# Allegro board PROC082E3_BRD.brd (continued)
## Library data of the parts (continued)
L1-L18 L20 L23 L25 L28-L30 = INDUCTOR
L19 L21 L22 L24 = INDUCTOR_DLW31S
R1-R52 R57 R61-R73 R78 R81-R99 R102 R106 R108-R119 R121-R123 R125 R128-R132 R135-R141 R144-R158 R160-R164 R166-R214 R222 R223 R228 R230 R232-R234 R236 R239 R241 R243-R245 R253-R259 = RESISTOR
R159 R165 = RESISTOR: signal model: RESISTOR_RES0402_22E_22E
TP1-TP45 TP50-TP53 TP55 TP56 = TESTPOINT
U1 U5 U10 U14 = TPD2E001DRLR_SOT-5
U3 U4 U7 U8 U12 U13 U16-U18 U23 U26 U27 = TPS25940_WQFN20_TI
U9 U24 U25 = DS90UB9702-Q1_VQFNP88
U19 = TPS62827DMQR_VSONHR6
U20 = CAT24C256WI-GT3_SOIC8
U21 = OSC4_ASDMB
U22 = LMK00105SQ_WQFN24
U28 = TPS54620_QFN14
U29-U31 = TPS74801DRCR_SON10
U32 = DS90UB971-Q1_VQFN32
U33 = TPS54318RTE_QFN16
U35 = LM25085A_WSON8
U36 = MOSFET_SI7123DN

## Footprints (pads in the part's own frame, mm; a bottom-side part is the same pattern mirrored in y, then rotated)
CAP0201_0-5
  rect 0.559x0.508 smd: 1(-0.38,0) 2(0.38,0)
CAP0402_0-75
  rect 0.559x0.635 smd: 1(-0.49,0) 2(0.49,0)
CAP0603_1
  rect 0.94x1.016 smd: 1(-0.8,0) 2(0.8,0)
CAP0805_1-5
  rect 1.143x1.448 smd: 1(-0.9,0) 2(0.9,0)
CAP1206_1
  rect 1.143x1.803 smd: 1(-1.5,0) 2(1.5,0)
CAP1206_2
  rect 1.143x1.803 smd: 1(-1.5,0) 2(1.5,0)
CAP1210_2-75
  rect 0.965x2.718 smd: 1(-1.65,0) 2(1.65,0)
CAP2220_5-5
  rect 0.813x5.41 smd: 1(-2.95,0) 2(2.95,0)
CAPAE_D8CASE_8
  rect 3.15x1.6 smd: 1(-2.9,0) 2(2.9,0)
CAPAE_E12CASE_12
  rect 3.759x2.159 smd: 1(-3.45,0) 2(3.45,0)
CAPT6032C_3
  rect 2.362x2.261 smd: 1(-2.45,0) 2(2.45,0)
CON_JACK4_D4S10A-400L5-Z_P_S_T_15-4
  rect 1.295x1.295 hole 0.813: 1(0,0)
  round 1.295 hole 0.813: 2(0,-2) 3(2,-2) 4(2,0)
  round 2.007 hole 1.575: SH1(-2,2) SH4(4,2)
  round 2.007 hole 1.219: SH2(-2,-4) SH3(4,-4)
CON_JACK5_59S10H-400T5-Z_P_S_T_12-5
  rect 1.702x1.702 hole 1.016: 1(0,0)
  round 2.108 hole 1.422: 2(-2.54,-2.54) 3(-2.54,2.54) 4(2.54,2.54) 5(2.54,-2.54)
CON_JACK5_59S20X-400T5-Z_P_R_T_10-1
  rect 2.21x2.21 hole 1.524: 1(0,0)
  round 2.565 hole 1.88: 2(-2.54,-2.54) 3(-2.54,2.54) 4(2.54,2.54) 5(2.54,-2.54)
CON_PMC2X20_QTH-020-01-D-DP-A_P_S_S_4-4
  round 0.889 hole 1.016 unplated: (-9.24,2.03) (9.24,2.03)
  rect 0.305x1.448 smd: 1(-7.25,3.08) 2(-7.25,-3.09) 3(-6.75,3.08) 4(-6.75,-3.09) 5(-5.75,3.08) 6(-5.75,-3.09) 7(-5.25,3.08) 8(-5.25,-3.09) 9(-4.25,3.08) 10(-4.25,-3.09) 11(-3.75,3.08) 12(-3.75,-3.09) 13(-2.75,3.08) 14(-2.75,-3.09) 15(-2.25,3.08) 16(-2.25,-3.09) 17(-1.25,3.08) 18(-1.25,-3.09) 19(-0.75,3.08) 20(-0.75,-3.09) 21(0.25,3.08) 22(0.25,-3.09) 23(0.75,3.08) 24(0.75,-3.09) 25(1.75,3.08) 26(1.75,-3.09) 27(2.25,3.08) 28(2.25,-3.09) 29(3.25,3.08) 30(3.25,-3.09) 31(3.75,3.08) 32(3.75,-3.09) 33(4.75,3.08) 34(4.75,-3.09) 35(5.25,3.08) 36(5.25,-3.09) 37(6.25,3.08) 38(6.25,-3.09) 39(6.75,3.08) 40(6.75,-3.09)
  rect 2.54x0.635 smd: SH1(-8.445,0) SH4(8.445,0)
  rect 4.699x0.635 smd: SH2(-3.175,0) SH3(3.175,0)
CON_TB1X2_1757242_P_R_T_8-6
  rect 2.108x2.108 hole 1.422: 1(0,0)
  round 2.108 hole 1.422: 2(-5.08,0)
DFN8_19-68_120X120_0-8_EP1-7X2-1
  rect 0.787x0.305 smd: 1(-1.5,0.75) 2(-1.5,0.25) 3(-1.5,-0.25) 4(-1.5,-0.75) 5(1.5,-0.75) 6(1.5,-0.25) 7(1.5,0.25) 8(1.5,0.75)
  rect 1.702x2.108 smd: 9(0,0)
DIO_SMC_2-7
  rect 2.21x3.099 smd: 1(-3.5,0) 2(3.5,0)
EMIFIL_BLM15A_0402_0-6
  rect 0.61x0.61 smd: 1(-0.46,0) 2(0.46,0)
EMIFIL_BLM18A_0603_1
  rect 0.991x0.991 smd: 1(-0.75,0) 2(0.75,0)
EMIFIL_BLM18R_0603
  rect 0.94x1.194 smd: 1(-0.825,0) 2(0.825,0)
FUSEH_154004_380X200_SMD_3-9
  rect 4.242x3.81 smd: 1(-3.19,0) 2(3.19,0)
IND4_DLW21H_90X60_SMD_1-4
  rect 0.889x0.356 smd: 1(-0.85,-0.425) 2(0.85,-0.425) 3(0.85,0.425) 4(-0.85,0.425)
IND_74437368022_410X410_SMD_4
  rect 4.089x3.505 smd: 1(-4.75,0) 2(4.75,0)
IND_74438357010_170X170_SMD_3-1
  rect 0.991x3.708 smd: 1(-1.185,0) 2(1.185,0)
IND_744040640047_250X250_SMD_4-5
  rect 1.803x5.69 smd: 1(-2.3,0) 2(2.3,0)
IND_MLZ2012N_90X60_SMD
  rect 0.813x1.219 smd: 1(-0.9,0) 2(0.9,0)
IND_XAL1010_460X410_SMD
  rect 2.388x8.992 smd: 1(-3.325,0) 2(3.325,0)
OSC4_ASDMB_100X85_SMD
  rect 0.66x0.864 smd: 1(-0.825,-0.775) 2(0.825,-0.775) 3(0.825,0.775) 4(-0.825,0.775)
POWERPAKSO8_SI7848BDP_240X200_1-2
  rect 1.27x0.61 smd: 1(-2.67,1.905) 2(-2.67,0.635) 3(-2.67,-0.635) 4(-2.67,-1.905)
  custom 1.105x1.105 smd: 5(1.045,0)
QFN14_19-68_145X145
  rect 0.838x0.279 smd: 1(-1.725,-0.75) 7(1.725,-0.75) 8(1.725,0.75) 14(-1.725,0.75)
  rect 0.279x0.838 smd: 2(-1,-1.725) 3(-0.5,-1.725) 4(0,-1.725) 5(0.5,-1.725) 6(1,-1.725) 9(1,1.725) 10(0.5,1.725) 11(0,1.725) 12(-0.5,1.725) 13(-1,1.725)
  custom 0.512x0.512 smd: 15(0,0)
QFN16_19-68_120X120_0-8_EP1-8
  rect 0.762x0.305 smd: 1(-1.5,0.75) 2(-1.5,0.25) 3(-1.5,-0.25) 4(-1.5,-0.75) 9(1.5,-0.75) 10(1.5,-0.25) 11(1.5,0.25) 12(1.5,0.75)
  rect 0.305x0.762 smd: 5(-0.75,-1.5) 6(-0.25,-1.5) 7(0.25,-1.5) 8(0.75,-1.5) 13(0.75,1.5) 14(0.25,1.5) 15(-0.25,1.5) 16(-0.75,1.5)
  rect 1.803x1.803 smd: 17(0,0)
QFN20_19-68_120X160_0-8
  rect 0.787x0.305 smd: 1(-1.5,1.25) 2(-1.5,0.75) 3(-1.5,0.25) 4(-1.5,-0.25) 5(-1.5,-0.75) 6(-1.5,-1.25) 11(1.5,-1.25) 12(1.5,-0.75) 13(1.5,-0.25) 14(1.5,0.25) 15(1.5,0.75) 16(1.5,1.25)
  rect 0.305x0.787 smd: 7(-0.75,-2) 8(-0.25,-2) 9(0.25,-2) 10(0.75,-2) 17(0.75,2) 18(0.25,2) 19(-0.25,2) 20(-0.75,2)
  rect 1.727x2.743 smd: 21(0,0)
QFN32_19-68_200X200_1_EP3-8
  rect 0.787x0.305 smd: 1(-2.5,1.75) 2(-2.5,1.25) 3(-2.5,0.75) 4(-2.5,0.25) 5(-2.5,-0.25) 6(-2.5,-0.75) 7(-2.5,-1.25) 8(-2.5,-1.75) 17(2.5,-1.75) 18(2.5,-1.25) 19(2.5,-0.75) 20(2.5,-0.25) 21(2.5,0.25) 22(2.5,0.75) 23(2.5,1.25) 24(2.5,1.75)
  rect 0.305x0.787 smd: 9(-1.75,-2.5) 10(-1.25,-2.5) 11(-0.75,-2.5) 12(-0.25,-2.5) 13(0.25,-2.5) 14(0.75,-2.5) 15(1.25,-2.5) 16(1.75,-2.5) 25(1.75,2.5) 26(1.25,2.5) 27(0.75,2.5) 28(0.25,2.5) 29(-0.25,2.5) 30(-0.75,2.5) 31(-1.25,2.5) 32(-1.75,2.5)
  rect 3.81x3.81 smd: 33(0,0)
QFN88_19-68_480X480_0-9_EP6-8
  rect 0.787x0.305 smd: 1(-6,5.25) 2(-6,4.75) 3(-6,4.25) 4(-6,3.75) 5(-6,3.25) 6(-6,2.75) 7(-6,2.25) 8(-6,1.75) 9(-6,1.25) 10(-6,0.75) 11(-6,0.25) 12(-6,-0.25) 13(-6,-0.75) 14(-6,-1.25) 15(-6,-1.75) 16(-6,-2.25) 17(-6,-2.75) 18(-6,-3.25) 19(-6,-3.75) 20(-6,-4.25) 21(-6,-4.75) 22(-6,-5.25) 45(6,-5.25) 46(6,-4.75) 47(6,-4.25) 48(6,-3.75) 49(6,-3.25) 50(6,-2.75) 51(6,-2.25) 52(6,-1.75) 53(6,-1.25) 54(6,-0.75) 55(6,-0.25) 56(6,0.25) 57(6,0.75) 58(6,1.25) 59(6,1.75) 60(6,2.25) 61(6,2.75) 62(6,3.25) 63(6,3.75) 64(6,4.25) 65(6,4.75) 66(6,5.25)
  rect 0.305x0.787 smd: 23(-5.25,-6) 24(-4.75,-6) 25(-4.25,-6) 26(-3.75,-6) 27(-3.25,-6) 28(-2.75,-6) 29(-2.25,-6) 30(-1.75,-6) 31(-1.25,-6) 32(-0.75,-6) 33(-0.25,-6) 34(0.25,-6) 35(0.75,-6) 36(1.25,-6) 37(1.75,-6) 38(2.25,-6) 39(2.75,-6) 40(3.25,-6) 41(3.75,-6) 42(4.25,-6) 43(4.75,-6) 44(5.25,-6) 67(5.25,6) 68(4.75,6) 69(4.25,6) 70(3.75,6) 71(3.25,6) 72(2.75,6) 73(2.25,6) 74(1.75,6) 75(1.25,6) 76(0.75,6) 77(0.25,6) 78(-0.25,6) 79(-0.75,6) 80(-1.25,6) 81(-1.75,6) 82(-2.25,6) 83(-2.75,6) 84(-3.25,6) 85(-3.75,6) 86(-4.25,6) 87(-4.75,6) 88(-5.25,6)
  rect 6.807x6.807 smd: 89(0,0)
RES0201_0-5
  rect 0.457x0.432 smd: 1(-0.33,0) 2(0.33,0)
RES0402_0-5
  rect 0.559x0.635 smd: 1(-0.49,0) 2(0.49,0)
RES0603_0-5
  rect 0.635x0.991 smd: 1(-0.74,0) 2(0.74,0)
RES1206_0-75
  rect 1.067x1.753 smd: 1(-1.45,0) 2(1.45,0)
SOIC8_1-8
  rect 2.007x0.61 smd: 1(-2.4,1.905) 2(-2.4,0.635) 3(-2.4,-0.635) 4(-2.4,-1.905) 5(2.4,-1.905) 6(2.4,-0.635) 7(2.4,0.635) 8(2.4,1.905)
SOT553-5_0-6
  rect 0.66x0.254 smd: 1(-0.74,0.5) 2(-0.74,0) 3(-0.74,-0.5) 4(0.74,-0.5) 5(0.74,0.5)
TO277-3_FSV10150V_1-2
  rect 1.143x1.448 smd: 1(-2.75,-0.985) 2(-2.75,0.985)
  rect 4.648x4.14 smd: 3(1,0)
TO-252AE-3_V20PW45C_1-6
  rect 1.397x1.905 smd: 1(2.29,-3.95) 2(-2.29,-3.95)
  rect 6.096x5.969 smd: 3(0,1.915)
TP30_SMD
  round 0.762 smd: 1(0,0)
TP40_SMD
  round 1.016 smd: 1(0,0)
TP_40X65
  round 1.651 hole 1.016: 1(0,0)
TP_CIR67D40_TH_4-6
  round 1.702 hole 1.016: 1(0,0)
unnamed#2
  round 3.073 hole 3.2 unplated: (0,0)
VSON10_TPS74801-Q1_120X120_1
  rect 0.61x0.229 smd: 1(-1.4,1) 2(-1.4,0.5) 3(-1.4,0) 4(-1.4,-0.5) 5(-1.4,-1) 6(1.4,-1) 7(1.4,-0.5) 8(1.4,0) 9(1.4,0.5) 10(1.4,1)
  custom 0.412x0.412 smd: 11(0,0)
VSONHR6_TPS62826_60X60_1
  rect 0.711x0.356 smd: 1(-0.65,0.5) 2(-0.65,0) 3(-0.65,-0.5)
  rect 0.991x0.203 smd: 4(0.45,-0.5) 5(0.45,0) 6(0.45,0.5)
WQFN24_19-68_160X160
  rect 0.813x0.305 smd: 1(-2,1.25) 2(-2,0.75) 3(-2,0.25) 4(-2,-0.25) 5(-2,-0.75) 6(-2,-1.25) 13(2,-1.25) 14(2,-0.75) 15(2,-0.25) 16(2,0.25) 17(2,0.75) 18(2,1.25)
  rect 0.305x0.813 smd: 7(-1.25,-2) 8(-0.75,-2) 9(-0.25,-2) 10(0.25,-2) 11(0.75,-2) 12(1.25,-2) 19(1.25,2) 20(0.75,2) 21(0.25,2) 22(-0.25,2) 23(-0.75,2) 24(-1.25,2)
  rect 2.692x2.692 smd: 25(0,0)

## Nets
DGND: C2.2 C3.2 C5.2 C6.2 C7.2 C8.2 C9.2 C10.2 C12.2 C13.2 C14.2 C16.2 C17.2 C18.2 C19.2 C20.2 C21.2 C22.2 C23.2 C24.2 C28.2 C29.2 C30.2 C31.2 C32.2 C33.2 C34.2 C36.2 C37.2 C38.2 C39.2 C40.2 C41.2 C43.2 C44.2 C46.2 C47.2 C49.2 C50.2 C51.2 C52.2 C54.2 C55.2 C57.2 C58.2 C59.2 C60.2 C61.2 C62.2 C63.2 C64.2 C65.2 C66.2 C67.2 C68.2 C69.2 C70.2 C71.2 C72.2 C73.2 C74.2 C75.2 C76.2 C77.2 C78.2 C79.2 C81.2 C82.2 C83.2 C84.2 C85.2 C86.2 C87.2 C89.2 C91.2 C92.2 C93.2 C94.2 C95.2 C96.2 C97.2 C98.2 C99.2 C101.2 C102.2 C103.2 C104.2 C106.2 C107.2 C108.2 C109.2 C110.2 C111.2 C112.2 C113.2 C114.2 C115.2 C116.2 C117.2 C118.2 C119.2 C120.2 C121.2 C122.2 C135.2 C136.2 C137.2 C138.2 C139.2 C140.2 C141.2 C142.2 C144.2 C145.2 C146.2 C147.2 C148.2 C149.2 C152.2 C156.2 C163.2 C164.2 C168.2 C169.2 C170.2 C172.2 C173.2 C174.2 C175.2 C176.2 C177.2 C183.2 C184.2 C185.2 C186.2 C187.2 C191.2 C195.2 C196.2 C203.2 C204.2 C205.2 C206.2 C207.2 C208.2 C209.2 C210.2 C211.2 C212.2 C213.2 C214.2 C215.2 C224.2 C225.2 C228.2 C229.2 C230.2 C231.2 C232.2 C233.2 C234.2 C235.2 C236.2 C238.2 C239.2 C240.2 C241.2 C242.2 C243.2 C244.2 C245.2 C250.2 C251.2 C252.2 C253.2 C254.2 C255.2 C256.2 C257.2 C258.2 C261.2 C263.2 C272.2 C273.2 C275.2 C278.2 C279.2 C280.2 C282.2 C287.2 C290.2 C291.2 C293.2 C294.2 C295.2 C296.2 C300.2 C301.2 C302.2 C303.2 C304.2 C309.2 C310.2 C311.2 C312.2 C313.2 C314.2 C316.2 C317.2 C318.2 C319.2 C321.2 C322.2 C323.2 C324.2 C325.2 C326.2 C327.2 C328.2 C329.2 C330.2 C331.2 C332.2 C333.2 C334.2 C335.2 C336.2 C339.2 C340.2 C341.2 C342.2 C343.2 C344.2 C345.2 C346.2 C347.2 C348.2 C350.2 C351.2 C352.1 C353.2 C354.2 C355.2 C356.2 C357.2 C358.2 C359.2 C360.2 C361.2 C362.2 C363.2 C364.2 C365.2 C366.2 C367.2 C368.2 C369.2 C370.2 C371.2 C372.2 C373.2 C374.2 C381.2 C382.2 C383.2 C384.2 C385.2 C386.2 C387.2 C390.2 C392.2 C398.2 C399.2 C400.2 C407.2 C409.2 C410.2 C411.2 C412.2 C413.2 C414.2 C415.2 C416.2 C417.2 C418.2 C419.2 C420.2 C421.2 C422.2 C423.2 C424.2 C425.2 C426.2 C427.2 C428.2 C429.2 C430.2 C431.2 C432.2 C433.2 C434.2 C435.2 C436.2 C437.2 C438.2 C439.2 C440.2 C441.2 C442.2 C443.2 C444.2 C445.2 C446.2 C447.2 C448.2 C449.2 C450.2 C451.2 C452.2 C453.2 C454.2 C455.2 C456.2 C457.2 C458.2 C459.2 C460.2 C461.2 C462.2 C463.2 C464.2 C465.2 C466.2 C467.2 C468.2 C469.2 C470.2 C471.2 C472.2 C473.2 C474.2 C485.2 C491.2 C492.2 C493.2 C495.2 C496.2 C500.2 C501.2 C502.2 C507.2 C508.2 C509.2 C510.2 C511.2 C512.2 C513.2 C514.2 C515.2 C516.2 C517.2 C518.2 C519.2 C521.2 C524.1 C525.2 C527.1 C528.2 C529.2 D2.2(ANODE) D3.1(A1) D3.2(A2) J1.12 J1.16 J1.24 J1.SH1 J1.SH2 J1.SH3 J1.SH4 J2.12 J2.16 J2.24 J2.SH1 J2.SH2 J2.SH3 J2.SH4 J3.SH1 J3.SH2 J3.SH3 J3.SH4 J4.2 J4.3 J4.4 J4.5 J5.2 J5.3 J5.4 J5.5 J6.SH1 J6.SH2 J6.SH3 J6.SH4 J7.2 J7.3 J7.4 J7.5 J8.2 J8.3 J8.4 J8.5 J9.SH1 J9.SH2 J9.SH3 J9.SH4 J10.2 J10.3 J10.4 J10.5 J11.2 J11.3 J11.4 J11.5 J12.SH1 J12.SH2 J12.SH3 J12.SH4 J13.2 J13.3 J13.4 J13.5 J14.2 J14.3 J14.4 J14.5 J15.2 J15.3 J15.4 J15.5 J16.2 J16.3 J16.4 J16.5 J17.2 J17.3 J17.4 J17.5 J18.2 J18.3 J18.4 J18.5 J19.1 J20.12 J20.16 J20.24 J20.SH1 J20.SH2 J20.SH3 J20.SH4 J21.2 J21.3 J21.4 J21.5 R1.1 R2.1 R3.2 R7.1 R8.1 R9.2 R16.2 R18.1 R19.1 R20.2 R21.2 R22.2 R26.1 R27.1 R28.2 R33.1 R34.2 R35.2 R36.2 R39.2 R42.2 R43.2 R44.1 R48.1 R50.1 R52.2 R61.2 R62.2 R65.2 R66.2 R69.2 R70.2 R73.2 R81.2 R83.2 R88.2 R89.2 R90.2 R93.2 R95.2 R106.2 R108.2 R111.2 R112.2 R115.2 R116.2 R119.2 R125.2 R128.2 R129.2 R130.2 R135.2 R136.2 R137.2 R140.2 R141.2 R147.2 R148.2 R152.2 R162.2 R166.2 R168.2 R181.2 R184.2 R187.2 R189.2 R192.2 R193.2 R194.2 R198.2 R200.1 R201.1 R202.1 R203.1 R204.1 R205.1 R207.2 R210.2 R213.2 R222.1 R232.2 R233.2 R239.2 R241.2 R254.2 R259.2 TP2.1(TP) TP36.1(TP) U1.4(GND) U3.1(DEVSLP) U3.3(PGTH) U3.16(GND) U3.21(EP) U4.1(DEVSLP) U4.3(PGTH) U4.16(GND) U4.21(EP) U5.4(GND) U7.1(DEVSLP) U7.3(PGTH) U7.16(GND) U7.21(EP) U8.1(DEVSLP) U8.3(PGTH) U8.16(GND) U8.21(EP) U9.89(GND) U10.4(GND) U12.1(DEVSLP) U12.3(PGTH) U12.16(GND) U12.21(EP) U13.1(DEVSLP) U13.3(PGTH) U13.16(GND) U13.21(EP) U14.4(GND) U16.1(DEVSLP) U16.3(PGTH) U16.16(GND) U16.21(EP) U17.1(DEVSLP) U17.3(PGTH) U17.16(GND) U17.21(EP) U18.1(DEVSLP) U18.3(PGTH) U18.16(GND) U18.21(EP) U19.4(GND) U20.4(VSS) U21.2(GND) U22.1(GND#1) U22.4(GND#4) U22.7(GND#7) U22.11(GND#11) U22.12(GND#12) U22.16(GND#16) U22.19(GND#19) U22.25(EP) U23.1(DEVSLP) U23.3(PGTH) U23.16(GND) U23.21(EP) U24.89(GND) U25.89(GND) U26.1(DEVSLP) U26.3(PGTH) U26.16(GND) U26.21(EP) U27.1(DEVSLP) U27.3(PGTH) U27.16(GND) U27.21(EP) U28.2(GND1) U28.3(GND2) U28.15(PAD) U29.6(GND) U29.11(PAD) U30.6(GND) U30.11(PAD) U31.6(GND) U31.11(PAD) U32.7(RES0) U32.33(GND) U33.3(GND1) U33.4(GND2) U33.5(AGND) U33.17(POWER_PAD) U35.4(GND) U35.9(EP)
VCC_1V1: C144.1 C147.1 C148.1 C152.1 C156.1 C318.1 C323.1 C327.1 C328.1 C329.1 C330.1 C333.1 C334.1 C343.1 C346.1 C495.1 C496.1 FL55.1 FL56.1 FL57.1 FL58.1 FL61.1 FL62.1 FL63.1 FL64.1 FL65.1 FL66.1 FL67.1 FL68.1 L28.2 R243.1 TP33.1(TP)
VCC_1V1_CBOOT: C484.1 U33.13(BOOT)
VCC_1V1_COMP: C502.1 R244.1 U33.7(COMP)
VCC_1V1_EN: R197.2 U33.15(EN)
VCC_1V1_FB: R239.1 R243.2 U33.6(VSENSE)
VCC_1V1_PG: R245.1 U33.14(PWRGD)
VCC_1V1_SW: C484.2 L28.1 U33.10(PH1) U33.11(PH2) U33.12(PH3)
VCC_1V8: C43.1 C44.1 C67.1 C68.1 C70.1 C71.1 C73.1 C74.1 C77.1 C79.1 C235.1 C236.1 C238.1 C239.1 C243.1 C473.1 C474.1 C508.1 FL25.1 FL39.1 FL40.1 FL41.1 FL42.1 FL59.1 FL76.2 FL78.2 FL80.1 L29.2 R223.1 R228.1 R234.1 TP1.1(TP) U19.3(FB) U22.2(VDDO#2) U22.6(VDDO#6)
VCC_1V8_EN: R145.1 U19.1(EN)
VCC_1V8_SW: L29.1 U19.5(SW)
VCC_3V3: C47.1 C59.1 C61.1 C113.1 C114.1 C509.1 C510.1 FL26.1 J1.30 J1.32 J1.34 J1.36 J2.30 J2.32 J2.34 J2.36 TP12.1(TP) U19.6(VIN)
VCC_12V: C135.1 C140.1 C163.1 C176.1 C209.1 C214.1 C225.1 C228.1 C234.1 C244.1 C303.1 C336.1 C341.1 C344.1 C347.1 C526.1 C527.2 C528.1 L30.2 R64.1 R67.1 R85.1 R91.1 R110.1 R113.1 R123.1 R132.1 R138.1 R164.1 R183.1 R191.1 R253.1 R258.1 TP56.1(TP) U3.9(IN1) U3.10(IN2) U3.11(IN3) U3.12(IN4) U3.13(IN5) U4.9(IN1) U4.10(IN2) U4.11(IN3) U4.12(IN4) U4.13(IN5) U7.9(IN1) U7.10(IN2) U7.11(IN3) U7.12(IN4) U7.13(IN5) U8.9(IN1) U8.10(IN2) U8.11(IN3) U8.12(IN4) U8.13(IN5) U12.9(IN1) U12.10(IN2) U12.11(IN3) U12.12(IN4) U12.13(IN5) U13.9(IN1) U13.10(IN2) U13.11(IN3) U13.12(IN4) U13.13(IN5) U16.9(IN1) U16.10(IN2) U16.11(IN3) U16.12(IN4) U16.13(IN5) U17.9(IN1) U17.10(IN2) U17.11(IN3) U17.12(IN4) U17.13(IN5) U18.9(IN1) U18.10(IN2) U18.11(IN3) U18.12(IN4) U18.13(IN5) U23.9(IN1) U23.10(IN2) U23.11(IN3) U23.12(IN4) U23.13(IN5) U26.9(IN1) U26.10(IN2) U26.11(IN3) U26.12(IN4) U26.13(IN5) U27.9(IN1) U27.10(IN2) U27.11(IN3) U27.12(IN4) U27.13(IN5) U28.4(PVIN1) U28.5(PVIN2) U28.6(VIN)
VCC_12V/20V_HDR: C352.2 C353.1 D2.1(CATHODE) F1.1 J19.2 TP35.1(TP)
VCC_12V_EXP_CONN: C66.1 C69.1 C118.1 C119.1 F2.1 J1.1 J1.3 J2.1 J2.3
VCC_CSI_IO: C62.1 C106.1 C115.1 C191.1 C195.1 C241.1 C302.1 C309.1 C310.1 FL60.1 J1.38 J1.40 J2.38 J2.40 R17.1 R46.1 R47.1 R86.2 R87.2 R99.2 R145.2 R146.1 R149.1 R151.1 R153.1 R170.2 R172.2 R176.2 R178.2 R179.2 R180.2 R197.1 R206.1 R209.1 R212.1 TP31.1(TP) U9.16(VDDIO) U20.8(VCC) U24.16(VDDIO) U25.16(VDDIO)
VDD1V8_P_HUB1: C41.1 C206.1 C207.1 FL25.2 U9.44(VDD18_P)
VDD1V8_P_HUB2: C83.1 C85.1 C258.1 FL39.2 U24.44(VDD18_P)
VDD1V8_P_HUB3: C89.1 C91.1 C109.1 FL42.2 U25.44(VDD18_P)
VDD11_CSI_HUB1: C146.1 C186.1 C187.1 C196.1 C204.1 C205.1 C208.1 C459.1 C460.1 C461.1 C462.1 C463.1 C464.1 C465.1 C466.1 C467.1 FL57.2 U9.29(VDD11_CSI#29) U9.30(VDD11_CSI#30) U9.43(VDD11_CSI#43) U9.46(VDD11_CSI#46) U9.59(VDD11_CSI#59)
VDD11_CSI_HUB2: C102.1 C255.1 C256.1 C263.1 C290.1 C291.1 C322.1 C431.1 C432.1 C433.1 C434.1 C435.1 C436.1 C437.1 C438.1 C439.1 FL62.2 U24.29(VDD11_CSI#29) U24.30(VDD11_CSI#30) U24.43(VDD11_CSI#43) U24.46(VDD11_CSI#46) U24.59(VDD11_CSI#59)
VDD11_CSI_HUB3: C110.1 C300.1 C311.1 C316.1 C319.1 C321.1 C325.1 C412.1 C413.1 C414.1 C415.1 C416.1 C417.1 C418.1 C419.1 C420.1 FL65.2 U25.29(VDD11_CSI#29) U25.30(VDD11_CSI#30) U25.43(VDD11_CSI#43) U25.46(VDD11_CSI#46) U25.59(VDD11_CSI#59)
VDD11_FPD_HUB1: C22.1 C149.1 C172.1 C174.1 C456.1 C457.1 C458.1 FL58.2 U9.72(VDD11_FPD#72) U9.83(VDD11_FPD#83)
VDD11_FPD_HUB2: C103.1 C272.1 C273.1 C326.1 C441.1 C442.1 C443.1 FL63.2 U24.72(VDD11_FPD#72) U24.83(VDD11_FPD#83)
VDD11_FPD_HUB3: C95.1 C97.1 C278.1 C324.1 C421.1 C422.1 C423.1 FL64.2 U25.72(VDD11_FPD#72) U25.83(VDD11_FPD#83)
VDD11_L_HUB1: C145.1 C183.1 C184.1 C185.1 C469.1 FL56.2 U9.5(VDD11_L#5) U9.62(VDD11_L#62)
VDD11_L_HUB2: C254.1 C301.1 C304.1 C332.1 C440.1 FL66.2 U24.5(VDD11_L#5) U24.62(VDD11_L#62)
VDD11_L_HUB3: C293.1 C294.1 C295.1 C342.1 C411.1 FL68.2 U25.5(VDD11_L#5) U25.62(VDD11_L#62)
VDD11_P0_HUB1: C141.1 C177.1 C203.1 C468.1 FL55.2 U9.45(VDD11_P#45)
VDD11_P0_HUB2: C82.1 C257.1 C317.1 C430.1 FL61.2 U24.45(VDD11_P#45)
VDD11_P0_HUB3: C279.1 C313.1 C331.1 C410.1 FL67.2 U25.45(VDD11_P#45)
VDD11_P1_HUB1: C369.1 C370.1 C371.1 FL70.2 U9.78(VDD11_P#78)
VDD11_P1_HUB2: C366.1 C367.1 C368.1 FL69.2 U24.78(VDD11_P#78)
VDD11_P1_HUB3: C372.1 C373.1 C374.1 FL71.2 U25.78(VDD11_P#78)
VDD18_FPD_HUB1: C23.1 C24.1 C28.1 C29.1 C173.1 C175.1 C240.1 C450.1 C451.1 C452.1 C453.1 C454.1 C455.1 FL59.2 R13.1 R15.1 U9.69(VDD18_FPD0) U9.75(VDD18_FPD1) U9.80(VDD18_FPD2) U9.86(VDD18_FPD3)
VDD18_FPD_HUB2: C78.1 C86.1 C96.1 C261.1 C280.1 C287.1 C296.1 C444.1 C445.1 C446.1 C447.1 C448.1 C449.1 FL40.2 R37.1 R38.1 U24.69(VDD18_FPD0) U24.75(VDD18_FPD1) U24.80(VDD18_FPD2) U24.86(VDD18_FPD3)
VDD18_FPD_HUB3: C84.1 C94.1 C98.1 C99.1 C101.1 C275.1 C282.1 C424.1 C425.1 C426.1 C427.1 C428.1 C429.1 FL41.2 R41.1 R171.1 U25.69(VDD18_FPD0) U25.75(VDD18_FPD1) U25.80(VDD18_FPD2) U25.86(VDD18_FPD3)
VDD_1P1_D: C390.1 C399.1 C470.1 U32.26(VDD_1P1_D)
VDD_1P1_DRV: C381.1 C382.1 C471.1 U32.15(VDD_1P1_DRV)
VDD_1P1_PLL: C385.1 C386.1 C472.1 U32.10(VDD_1P1_PLL)
VDD_1P8_D: C392.1 C400.1 FL78.1 U32.25(VDD_1P8_D)
VDD_1P8_DRV: C387.1 C398.1 FL76.1 U32.16(VDD_1P8_DRV)
VDD_1P8_PLL: C383.1 C384.1 C408.2 FL80.2 U32.11(VDD_1P8_PLL)
VDD_1V1_HUB1: C356.1 C516.1 FL70.1 R208.1 TP51.1(TP) U29.9(OUT1) U29.10(OUT2)
VDD_1V1_HUB1_EN: R206.2 U29.5(EN)
VDD_1V1_HUB1_FB: R207.1 R208.2 U29.8(FB)
VDD_1V1_HUB1_PG: TP38.1(TP) U29.3(PG)
VDD_1V1_HUB1_SS: C363.1 U29.7(SS)
VDD_1V1_HUB2: C359.1 C513.1 FL69.1 R211.1 TP52.1(TP) U30.9(OUT1) U30.10(OUT2)
VDD_1V1_HUB2_EN: R209.2 U30.5(EN)
VDD_1V1_HUB2_FB: R210.1 R211.2 U30.8(FB)
VDD_1V1_HUB2_PG: TP39.1(TP) U30.3(PG)
VDD_1V1_HUB2_SS: C364.1 U30.7(SS)
VDD_1V1_HUB3: C362.1 C519.1 FL71.1 R214.1 TP53.1(TP) U31.9(OUT1) U31.10(OUT2)
VDD_1V1_HUB3_EN: R212.2 U31.5(EN)
VDD_1V1_HUB3_FB: R213.1 R214.2 U31.8(FB)
VDD_1V1_HUB3_PG: TP40.1(TP) U31.3(PG)
VDD_1V1_HUB3_SS: C365.1 U31.7(SS)
VDD_3V3: C46.1 C72.1 C75.1 FL26.2 U22.8(VDD#8) U22.23(VDD#23)
971_GPIO0_TP: TP42.1(TP) U32.17(GPIO_0)
971_GPIO1_TP: TP43.1(TP) U32.18(GPIO_1)
971_GPIO2_TP: TP44.1(TP) U32.27(GPIO_2)
971_GPIO3_TP: TP45.1(TP) U32.28(GPIO_3)
971_IDX/CLK_OUT: R232.1 R234.2 TP41.1(TP) U32.19(CLK_OUT/IDX)
971_MODE: R228.2 R233.1 U32.21(MODE)
971_PDB: C409.1 R223.2 U32.8(PDB)
971_REF CLK: R230.2 R236.1
971_REF CLK_R: R230.1 U22.3(CLKOUT0)
C_CAM5_RIN0_N: C262.1 R33.2
C_CAM5_RIN0_P: C260.1 FL38.2 J15.1
C_CAM6_RIN1_N: C281.1 R44.2
C_CAM6_RIN1_P: C274.1 FL46.2 J16.1
C_CAM7_RIN2_N: C288.1 R48.2
C_CAM7_RIN2_P: C285.1 FL50.2 J17.1
C_CAM8_RIN3_N: C297.1 R50.2
C_CAM8_RIN3_P: C292.1 FL54.2 J18.1
C_CAM9_RIN0_N: C270.1 R26.2
C_CAM9_RIN0_P: C271.1 FL27.2 J14.1
C_CAM10_RIN1_N: C268.1 R18.2
C_CAM10_RIN1_P: C269.1 FL17.2 J11.1
C_CAM11_RIN2_N: C266.1 R7.2
C_CAM11_RIN2_P: C267.1 FL9.2 J8.1
C_CAM12_RIN3_N: C264.1 R1.2
C_CAM12_RIN3_P: C265.1 FL1.2 J5.1
C_DOUT_N: C406.1 R222.2
C_DOUT_P: C405.1 J21.1
C_HUB1_CMLOUT0N: C181.2 U9.63(CML0N)
C_HUB1_CMLOUT0P: C179.2 U9.64(CML0P)
C_HUB1_CMLOUT1N: C167.2 U9.65(CML1N)
C_HUB1_CMLOUT1P: C166.2 U9.66(CML1P)
C_HUB1_CMLOUT2N: C178.2 U9.2(CML2N)
C_HUB1_CMLOUT2P: C171.2 U9.1(CML2P)
C_HUB1_CMLOUT3N: C182.2 U9.4(CML3N)
C_HUB1_CMLOUT3P: C180.2 U9.3(CML3P)
C_HUB2_CMLOUT0N: C249.2 U24.63(CML0N)
C_HUB2_CMLOUT0P: C248.2 U24.64(CML0P)
C_HUB2_CMLOUT1N: C247.2 U24.65(CML1N)
C_HUB2_CMLOUT1P: C246.2 U24.66(CML1P)
C_HUB2_CMLOUT2N: C306.2 U24.2(CML2N)
C_HUB2_CMLOUT2P: C305.2 U24.1(CML2P)
C_HUB2_CMLOUT3N: C308.2 U24.4(CML3N)
C_HUB2_CMLOUT3P: C307.2 U24.3(CML3P)
C_HUB3_CMLOUT0N: C298.2 U25.63(CML0N)
C_HUB3_CMLOUT0P: C299.2 U25.64(CML0P)
C_HUB3_CMLOUT1N: C284.2 U25.65(CML1N)
C_HUB3_CMLOUT1P: C283.2 U25.66(CML1P)
C_HUB3_CMLOUT2N: C276.2 U25.2(CML2N)
C_HUB3_CMLOUT2P: C277.2 U25.1(CML2P)
C_HUB3_CMLOUT3N: C289.2 U25.4(CML3N)
C_HUB3_CMLOUT3P: C286.2 U25.3(CML3P)
CAM1_RIN_N: C132.1 R2.2
CAM1_RIN_P: C133.1 FL2.2 J4.1
CAM2_RIN_N: C160.1 R8.2
CAM2_RIN_P: C161.1 FL10.2 J7.1
CAM3_RIN_N: C198.1 R19.2
CAM3_RIN_P: C201.1 FL18.2 J10.1
CAM4_RIN_N: C223.1 R27.2
CAM4_RIN_P: C226.1 FL28.2 J13.1
CAM5_RIN0_N: C262.2 U24.71(RIN0-)
CAM5_RIN0_P: C260.2 U24.70(RIN0+)
CAM6_RIN1_N: C281.2 U24.74(RIN1-)
CAM6_RIN1_P: C274.2 U24.73(RIN1+)
CAM7_RIN2_N: C288.2 U24.82(RIN2-)
CAM7_RIN2_P: C285.2 U24.81(RIN2+)
CAM8_RIN3_N: C297.2 U24.85(RIN3-)
CAM8_RIN3_P: C292.2 U24.84(RIN3+)
CAM9_RIN0_N: C270.2 U25.71(RIN0-)
CAM9_RIN0_P: C271.2 U25.70(RIN0+)
CAM10_RIN1_N: C268.2 U25.74(RIN1-)
CAM10_RIN1_P: C269.2 U25.73(RIN1+)
CAM11_RIN2_N: C266.2 U25.82(RIN2-)
CAM11_RIN2_P: C267.2 U25.81(RIN2+)
CAM12_RIN3_N: C264.2 U25.85(RIN3-)
CAM12_RIN3_P: C265.2 U25.84(RIN3+)
CAM_FLASH_EN: J2.20
CAM_XTRIG: J1.20
CLK_BUF_OE: R167.1 U22.24(OE)
CLK_BUF_SEL: R157.1 U22.22(SEL)
CSI0_CLK_N: J2.7 U9.31(CSI0_CLK0N)
CSI0_CLK_P: J2.5 U9.32(CSI0_CLK0P)
CSI0_D0_N: J2.11 U9.33(CSI0_D0N)
CSI0_D0_P: J2.9 U9.34(CSI0_D0P)
CSI0_D1_N: J2.15 U9.35(CSI0_D1N)
CSI0_D1_P: J2.13 U9.36(CSI0_D1P)
CSI0_D2_N: J2.19 U9.39(CSI0_D2N)
CSI0_D2_P: J2.17 U9.40(CSI0_D2P)
CSI0_D3_N: J2.23 U9.41(CSI0_D3N)
CSI0_D3_P: J2.21 U9.42(CSI0_D3P)
CSI1_CLK_N: J2.27 U24.31(CSI0_CLK0N)
CSI1_CLK_P: J2.25 U24.32(CSI0_CLK0P)
CSI1_D0_N: J2.31 U24.33(CSI0_D0N)
CSI1_D0_P: J2.29 U24.34(CSI0_D0P)
CSI1_D1_N: J2.35 U24.35(CSI0_D1N)
CSI1_D1_P: J2.33 U24.36(CSI0_D1P)
CSI1_D2_N: J2.39 U24.39(CSI0_D2N)
CSI1_D2_P: J2.37 U24.40(CSI0_D2P)
CSI1_D3_N: J2.28 U24.41(CSI0_D3N)
CSI1_D3_P: J2.26 U24.42(CSI0_D3P)
CSI2_0_CLK_N: J20.27 U9.17(CSI2_CLK0N)
CSI2_0_CLK_P: J20.25 U9.18(CSI2_CLK0P)
CSI2_0_D0_N: J20.31 U9.19(CSI2_D0N)
CSI2_0_D0_P: J20.29 U9.20(CSI2_D0P)
CSI2_0_D1_N: J20.35 U9.21(CSI2_D1N)
CSI2_0_D1_P: J20.33 U9.22(CSI2_D1P)
CSI2_0_D2_N: J20.39 U9.25(CSI2_D2N)
CSI2_0_D2_P: J20.37 U9.26(CSI2_D2P)
CSI2_0_D3_N: J20.28 U9.27(CSI2_D3N)
CSI2_0_D3_P: J20.26 U9.28(CSI2_D3P)
CSI2_CLK_N: J1.7 U25.31(CSI0_CLK0N)
CSI2_CLK_P: J1.5 U25.32(CSI0_CLK0P)
CSI2_D0_N: J1.11 U25.33(CSI0_D0N)
CSI2_D0_P: J1.9 U25.34(CSI0_D0P)
CSI2_D1_N: J1.15 U25.35(CSI0_D1N)
CSI2_D1_P: J1.13 U25.36(CSI0_D1P)
CSI2_D2_N: J1.19 U25.39(CSI0_D2N)
CSI2_D2_P: J1.17 U25.40(CSI0_D2P)
CSI2_D3_N: J1.23 U25.41(CSI0_D3N)
CSI2_D3_P: J1.21 U25.42(CSI0_D3P)
CSI_TX_CLK_N: J20.7 U32.6(CSI_CLKN)
CSI_TX_CLK_P: J20.5 U32.5(CSI_CLKP)
CSI_TX_D0_N: J20.11 U32.4(CSI_D0N)
CSI_TX_D0_P: J20.9 U32.3(CSI_D0P)
CSI_TX_D1_N: J20.15 U32.2(CSI_D1N)
CSI_TX_D1_P: J20.13 U32.1(CSI_D1P)
CSI_TX_D2_N: J20.19 U32.32(CSI_D2N)
CSI_TX_D2_P: J20.17 U32.31(CSI_D2P)
CSI_TX_D3_N: J20.23 U32.30(CSI_D3N)
CSI_TX_D3_P: J20.21 U32.29(CSI_D3P)
DOUT_N: C406.2 U32.13(DOUT-)
DOUT_P: C405.2 U32.14(DOUT+)
EEPROM_A0: R151.2 R152.1 U20.1(A0)
EEPROM_A1: R148.1 R149.2 U20.2(A1)
EEPROM_A2: R146.2 R147.1 U20.3(A2)
EEPROM_WP: R153.2 U20.7(WP)
GPIO0_HUB1: R204.2 U9.6(GPIO[0])
GPIO0_HUB2: R202.2 U24.6(GPIO[0])
GPIO0_HUB3: R200.2 U25.6(GPIO[0])
GPIO1_HUB1: R205.2 U9.7(GPIO[1])
GPIO1_HUB2: R203.2 U24.7(GPIO[1])
GPIO1_HUB3: R201.2 U25.7(GPIO[1])
HUB1_CK_O: TP11.1(TP) U9.14(CK_O/GPIO[8])
HUB1_CMLOUT0N: C181.1 R96.1 TP9.1(TP)
HUB1_CMLOUT0P: C179.1 R96.2 TP10.1(TP)
HUB1_CMLOUT1N: C167.1 R82.1 TP4.1(TP)
HUB1_CMLOUT1P: C166.1 R82.2 TP3.1(TP)
HUB1_CMLOUT2N: C178.1 R94.1 TP6.1(TP)
HUB1_CMLOUT2P: C171.1 R94.2 TP5.1(TP)
HUB1_CMLOUT3N: C182.1 R98.1 TP8.1(TP)
HUB1_CMLOUT3P: C180.1 R98.2 TP7.1(TP)
HUB1_I2C_SCL2: R87.1 U9.87(I2C_SCL2/GPIO[10])
HUB1_I2C_SDA2: R86.1 U9.88(I2C_SDA2/GPIO[9])
HUB1_IDX: R15.2 R16.1 U9.76(IDX)
HUB1_INTBN: J2.6 R99.1 U9.9(INTB/GPIO[3])
HUB1_LPF: C30.1 U9.77(LPF)
HUB1_MODE: R13.2 R88.1 U9.79(MODE)
HUB1_REF CLK: R156.2 U9.15(REFCLK)
HUB1_REF CLK_R: R156.1 U22.13(CLKOUT2)
HUB1_RIN0_N: C125.1 C132.2 U9.71(RIN0-)
HUB1_RIN0_P: C126.1 C133.2 U9.70(RIN0+)
HUB1_RIN1_N: C151.1 C160.2 U9.74(RIN1-)
HUB1_RIN1_P: C154.1 C161.2 U9.73(RIN1+)
HUB1_RIN2_N: C189.1 C198.2 U9.82(RIN2-)
HUB1_RIN2_P: C190.1 C201.2 U9.81(RIN2+)
HUB1_RIN3_N: C218.1 C223.2 U9.85(RIN3-)
HUB1_RIN3_P: C219.1 C226.2 U9.84(RIN3+)
HUB1_SYNC: J2.18 U9.8(GPIO[2])
HUB2_CK_O: TP26.1(TP) U24.14(CK_O/GPIO[8])
HUB2_CMLOUT0N: C249.1 R161.1 TP14.1(TP)
HUB2_CMLOUT0P: C248.1 R161.2 TP13.1(TP)
HUB2_CMLOUT1N: C247.1 R160.1 TP16.1(TP)
HUB2_CMLOUT1P: C246.1 R160.2 TP15.1(TP)
HUB2_CMLOUT2N: C306.1 R185.1 TP28.1(TP)
HUB2_CMLOUT2P: C305.1 R185.2 TP27.1(TP)
HUB2_CMLOUT3N: C308.1 R186.1 TP30.1(TP)
HUB2_CMLOUT3P: C307.1 R186.2 TP29.1(TP)
HUB2_I2C_SCL2: R176.1 U24.87(I2C_SCL2/GPIO[10])
HUB2_I2C_SDA2: R179.1 U24.88(I2C_SDA2/GPIO[9])
HUB2_IDX: R34.1 R37.2 U24.76(IDX)
HUB2_INTBN: J2.8 R180.1 U24.9(INTB/GPIO[3])
HUB2_LPF: C93.1 U24.77(LPF)
HUB2_MODE: R35.1 R38.2 U24.79(MODE)
HUB2_REF CLK: R155.2 U24.15(REFCLK)
HUB2_REF CLK_R: R155.1 U22.15(CLKOUT3)
HUB2_SYNC: J2.22 U24.8(GPIO[2])
HUB3_CK_O: TP23.1(TP) U25.14(CK_O/GPIO[8])
HUB3_CMLOUT0N: C298.1 R177.1 TP24.1(TP)
HUB3_CMLOUT0P: C299.1 R177.2 TP25.1(TP)
HUB3_CMLOUT1N: C284.1 R174.1 TP20.1(TP)
HUB3_CMLOUT1P: C283.1 R174.2 TP19.1(TP)
HUB3_CMLOUT2N: C276.1 R173.1 TP17.1(TP)
HUB3_CMLOUT2P: C277.1 R173.2 TP18.1(TP)
HUB3_CMLOUT3N: C289.1 R175.1 TP22.1(TP)
HUB3_CMLOUT3P: C286.1 R175.2 TP21.1(TP)
HUB3_I2C_SCL2: R170.1 U25.87(I2C_SCL2/GPIO[10])
HUB3_I2C_SDA2: R172.1 U25.88(I2C_SDA2/GPIO[9])
HUB3_IDX: R39.1 R171.2 U25.76(IDX)
HUB3_INTBN: J1.8 R178.1 U25.9(INTB/GPIO[3])
HUB3_LPF: C104.1 U25.77(LPF)
HUB3_MODE: R41.2 R42.1 U25.79(MODE)
HUB3_REF CLK: R154.2 U25.15(REFCLK)
HUB3_REF CLK_R: R154.1 U22.17(CLKOUT4)
HUB3_SYNC: J1.18 U25.8(GPIO[2])
HUB_RESETN: C31.1 J2.14 R17.2 U9.61(PDB) U24.61(PDB) U25.61(PDB)
LM25085A_FB: C526.2 R258.2 R259.1 U35.3(FB)
LM25085A_ISEN: R255.2 U35.5(ISEN) U36.5(D1)
LPF1_CAP: C408.1 U32.9(LPF1)
LPF2_CAP: C407.1 U32.12(LPF2)
OSC_REF CLK: R159.1 U21.3(OUTPUT)
R_971_REF CLK: R236.2 U32.20(CLKIN)
RDR1_RIN_N: J3.4 L19.3(OUT1) U1.3(IO1)
RDR1_RIN_P: J3.2 L19.2(IN2) U1.2(NC) U1.5(IO2)
RDR2_RIN_N: J6.4 L21.3(OUT1) U5.2(NC) U5.5(IO2)
RDR2_RIN_P: J6.2 L21.2(IN2) U5.3(IO1)
RDR3_RIN_N: J9.4 L22.3(OUT1) U10.2(NC) U10.5(IO2)
RDR3_RIN_P: J9.2 L22.2(IN2) U10.3(IO1)
RDR4_RIN_N: J12.4 L24.3(OUT1) U14.2(NC) U14.5(IO2)
RDR4_RIN_P: J12.2 L24.2(IN2) U14.3(IO1)
REF_CLK: J2.10 R165.1
REF_CLK_R: R159.2 R165.2 U22.9(OSCIN)
SOC_I2C6_SCL: J2.2 R47.2 U9.68(I2C_SCL) U20.6(SCL) U24.68(I2C_SCL) U25.68(I2C_SCL) U32.24(I2C_SCL)
SOC_I2C6_SDA: J2.4 R46.2 U9.67(I2C_SDA) U20.5(SDA) U24.67(I2C_SDA) U25.67(I2C_SDA) U32.23(I2C_SDA)
T_RDR1_RIN_N: C125.2 L19.4(OUT2)
T_RDR1_RIN_P: C126.2 L19.1(IN1)
T_RDR2_RIN_N: C151.2 L21.4(OUT2)
T_RDR2_RIN_P: C154.2 L21.1(IN1)
T_RDR3_RIN_N: C189.2 L22.4(OUT2)
T_RDR3_RIN_P: C190.2 L22.1(IN1)
T_RDR4_RIN_N: C218.2 L24.4(OUT2)
T_RDR4_RIN_P: C219.2 L24.1(IN1)
TESTEN1: R22.1 U9.60(TESTEN)
TESTEN2: R36.1 U24.60(TESTEN)
TESTEN3: R43.1 U25.60(TESTEN)
TP_CLKOUT1: TP50.1(TP) U22.5(CLKOUT1)
V_CAM5: C60.1 C64.1 C232.1 FL35.1 R150.1 U18.4(OUT1) U18.5(OUT2) U18.6(OUT3) U18.7(OUT4) U18.8(OUT5)
V_CAM6: C76.1 C81.1 C250.1 FL43.1 R169.1 U23.4(OUT1) U23.5(OUT2) U23.6(OUT3) U23.7(OUT4) U23.8(OUT5)
V_CAM7: C107.1 C108.1 C314.1 FL47.1 R188.1 U26.4(OUT1) U26.5(OUT2) U26.6(OUT3) U26.7(OUT4) U26.8(OUT5)
V_CAM8: C116.1 C117.1 C340.1 FL51.1 R195.1 U27.4(OUT1) U27.5(OUT2) U27.6(OUT3) U27.7(OUT4) U27.8(OUT5)
V_CAM9: C57.1 C58.1 C224.1 FL34.1 R121.1 U16.4(OUT1) U16.5(OUT2) U16.6(OUT3) U16.7(OUT4) U16.8(OUT5)
V_CAM10: C38.1 C39.1 C211.1 FL23.1 R102.1 U12.4(OUT1) U12.5(OUT2) U12.6(OUT3) U12.7(OUT4) U12.8(OUT5)
V_CAM11: C18.1 C19.1 C168.1 FL15.1 R78.1 U7.4(OUT1) U7.5(OUT2) U7.6(OUT3) U7.7(OUT4) U7.8(OUT5)
V_CAM12: C9.1 C10.1 C137.1 FL7.1 R57.1 U3.4(OUT1) U3.5(OUT2) U3.6(OUT3) U3.7(OUT4) U3.8(OUT5)
V_RAD/CAM1: C6.1 C7.1 C122.1 C138.1 FL8.1 R4.1 R51.1 R71.1 U4.4(OUT1) U4.5(OUT2) U4.6(OUT3) U4.7(OUT4) U4.8(OUT5)
V_RAD/CAM1_CON1: C123.2 J3.1 L18.1 U1.1(VCC)
V_RAD/CAM1_CON3: C1.2 J3.3 L1.1
V_RAD/CAM2: C16.1 C20.1 C142.1 C169.1 FL16.1 R10.1 R72.1 R97.1 U8.4(OUT1) U8.5(OUT2) U8.6(OUT3) U8.7(OUT4) U8.8(OUT5)
V_RAD/CAM2_CON1: C143.2 J6.1 L20.1
V_RAD/CAM2_CON3: C11.2 J6.3 L4.1 U5.1(VCC)
V_RAD/CAM3: C21.1 C36.1 C40.1 C212.1 FL24.1 R14.1 R23.1 R118.1 U13.4(OUT1) U13.5(OUT2) U13.6(OUT3) U13.7(OUT4) U13.8(OUT5)
V_RAD/CAM3_CON1: C27.2 J9.1 L8.1 U10.1(VCC)
V_RAD/CAM3_CON3: C25.2 J9.3 L7.1
V_RAD/CAM4: C51.1 C54.1 C215.1 C229.1 FL30.1 R29.1 R117.1 R144.1 U17.4(OUT1) U17.5(OUT2) U17.6(OUT3) U17.7(OUT4) U17.8(OUT5)
V_RAD/CAM4_CON1: C45.2 J12.1 L11.1 U14.1(VCC)
V_RAD/CAM4_CON3: C216.2 J12.3 L23.1
VCC_1V1_RT/CLK: R241.1 U33.8(RT/CLK)
VCC_1V1_SS/TR: C500.1 U33.9(SS/TR)
VIO_CLK_OSC: C242.1 C245.1 C251.1 C252.1 FL60.2 R157.2 R158.1 R167.2 U21.4(VDD) U22.14(VDDO#14) U22.18(VDDO#18)
VMAIN: C351.1 C521.1 C522.2 C523.1 C524.2 C525.1 C529.1 D1.3(K) F1.2 R255.1 R256.2 R257.1 TP34.1(TP) U35.8(VIN)
VREG_3V3: C335.1 C354.1 C355.1 C357.1 C358.1 C360.1 C361.1 C485.1 C491.1 C492.1 C493.1 C507.1 C511.1 C512.1 C514.1 C515.1 C517.1 C518.1 L25.2 R199.1 R245.2 TP55.1(TP) U29.1(IN1) U29.2(IN2) U29.4(BIAS) U30.1(IN1) U30.2(IN2) U30.4(BIAS) U31.1(IN1) U31.2(IN2) U31.4(BIAS) U33.1(VIN1) U33.2(VIN2) U33.16(VIN3)
VREG_3V3_CBOOT: C338.1 U28.13(BOOT)
VREG_3V3_COMP: C345.1 R196.1 U28.8(COMP)
VREG_3V3_EN: R253.2 R254.1 U28.10(EN)
VREG_3V3_FB: R198.1 R199.2 U28.7(VSENSE)
VREG_3V3_PG: TP32.1(TP) U28.14(PWRGD)
VREG_3V3_RT/CLK: R193.1 U28.1(RT/CLK)
VREG_3V3_SS/TR: C350.1 U28.9(SS/TR)
VREG_3V3_SW: C338.2 L25.1 U28.11(PH1) U28.12(PH2)
N23276823: FL5.1 L3.2 R6.2
N23276832: C5.1 C8.1 FL8.2 L3.1 R6.1
N23276850: FL2.1 FL6.2
N23276958: FL5.2 FL6.1
N23280059: C1.1 R3.1
N23280068: C123.1 R52.1
N23280320: L1.2 R4.2
N23280326: L18.2 R51.2
N23290514: FL13.1 L6.2 R12.2
N23290520: C14.1 C17.1 FL16.2 L6.1 R12.1
N23290544: FL10.1 FL14.2
N23290557: FL13.2 FL14.1
N23290886: C11.1 R9.1
N23290898: C143.1 R73.1
N23290929: L4.2 R10.2
N23290931: L20.2 R72.2
N23296098: FL21.1 L10.2 R25.2
N23296110: C34.1 C37.1 FL24.2 L10.1 R25.1
N23296124: FL18.1 FL22.2
N23296133: FL21.2 FL22.1
N23296478: C27.1 R21.1
N23296488: C25.1 R20.1
N23296513: L7.2 R14.2
N23296515: L8.2 R23.2
N23301401: FL32.1 L13.2 R31.2
N23301413: C52.1 C55.1 FL30.2 L13.1 R31.1
N23301427: FL28.1 FL33.2
N23301436: FL32.2 FL33.1
N23301766: C45.1 R28.1
N23301784: C216.1 R119.1
N23301809: L23.2 R117.2
N23301811: L11.2 R29.2
N23304842: FL37.1 L14.2 R32.2
N23304854: C63.1 C65.1 FL35.2 L14.1 R32.1
N23304868: FL36.2 FL38.1
N23304877: FL36.1 FL37.2
N23306297: FL45.1 L15.2 R40.2
N23306309: C87.1 C92.1 FL43.2 L15.1 R40.1
N23306323: FL44.2 FL46.1
N23306330: FL44.1 FL45.2
N23308323: FL49.1 L16.2 R45.2
N23308335: C111.1 C112.1 FL47.2 L16.1 R45.1
N23308349: FL48.2 FL50.1
N23308356: FL48.1 FL49.2
N23309323: FL53.1 L17.2 R49.2
N23309335: C120.1 C121.1 FL51.2 L17.1 R49.1
N23309349: FL52.2 FL54.1
N23309356: FL52.1 FL53.2
N23311355: R71.2 U4.20(F\L\T\)
N23312712: R63.1 R64.2 U4.14(EN/UVLO)
N23312989: R62.1 R63.2 U4.15(OVP)
N23313210: C139.1 U4.18(DVDT)
N23313421: R65.1 U4.17(ILIM)
N23314293: R70.1 U4.19(IMON)
N23315548: R84.1 R85.2 U8.14(EN/UVLO)
N23315552: R83.1 R84.2 U8.15(OVP)
N23315587: C170.1 U8.18(DVDT)
N23315604: R89.1 U8.17(ILIM)
N23315632: R95.1 U8.19(IMON)
N23315748: R97.2 U8.20(F\L\T\)
N23316320: R109.1 R110.2 U13.14(EN/UVLO)
N23316340: R108.1 R109.2 U13.15(OVP)
N23316375: C213.1 U13.18(DVDT)
N23316392: R111.1 U13.17(ILIM)
N23316420: R116.1 U13.19(IMON)
N23316528: R118.2 U13.20(F\L\T\)
N23317098: R122.1 R123.2 U17.14(EN/UVLO)
N23317110: R122.2 R125.1 U17.15(OVP)
N23317144: C230.1 U17.18(DVDT)
N23317167: R129.1 U17.17(ILIM)
N23317190: R137.1 U17.19(IMON)
N23317306: R144.2 U17.20(F\L\T\)
N23319711: R131.1 R132.2 U18.14(EN/UVLO)
N23319731: R130.1 R131.2 U18.15(OVP)
N23319762: C233.1 U18.18(DVDT)
N23319779: R135.1 U18.17(ILIM)
N23319811: R141.1 U18.19(IMON)
N23319923: R150.2 U18.20(F\L\T\)
N23320313: R163.1 R164.2 U23.14(EN/UVLO)
N23320339: R162.1 R163.2 U23.15(OVP)
N23320379: C253.1 U23.18(DVDT)
N23320395: R166.1 U23.17(ILIM)
N23320426: R168.1 U23.19(IMON)
N23320539: R169.2 U23.20(F\L\T\)
N23320826: R182.1 R183.2 U26.14(EN/UVLO)
N23320852: R181.1 R182.2 U26.15(OVP)
N23320892: C312.1 U26.18(DVDT)
N23320908: R184.1 U26.17(ILIM)
N23320939: R187.1 U26.19(IMON)
N23321052: R188.2 U26.20(F\L\T\)
N23321397: R190.1 R191.2 U27.14(EN/UVLO)
N23321423: R189.1 R190.2 U27.15(OVP)
N23321463: C339.1 U27.18(DVDT)
N23321479: R192.1 U27.17(ILIM)
N23321510: R194.1 U27.19(IMON)
N23321623: R195.2 U27.20(F\L\T\)
N23545074: FL29.1 L12.2 R30.2
N23545086: C49.1 C50.1 FL34.2 L12.1 R30.1
N23545100: FL27.1 FL31.2
N23545106: FL29.2 FL31.1
N23545339: FL19.1 L9.2 R24.2
N23545354: C32.1 C33.1 FL23.2 L9.1 R24.1
N23545368: FL17.1 FL20.2
N23545374: FL19.2 FL20.1
N23545556: R138.2 R139.1 U16.14(EN/UVLO)
N23545576: R139.2 R140.1 U16.15(OVP)
N23545607: C231.1 U16.18(DVDT)
N23545624: R136.1 U16.17(ILIM)
N23545648: R128.1 U16.19(IMON)
N23545749: R121.2 U16.20(F\L\T\)
N23545784: R113.2 R114.1 U12.14(EN/UVLO)
N23545810: R114.2 R115.1 U12.15(OVP)
N23545851: C210.1 U12.18(DVDT)
N23545860: R112.1 U12.17(ILIM)
N23545892: R106.1 U12.19(IMON)
N23546004: R102.2 U12.20(F\L\T\)
N23546024: R91.2 R92.1 U7.14(EN/UVLO)
N23546050: R92.2 R93.1 U7.15(OVP)
N23546087: C164.1 U7.18(DVDT)
N23546094: R90.1 U7.17(ILIM)
N23546126: R81.1 U7.19(IMON)
N23546235: R78.2 U7.20(F\L\T\)
N23546296: FL11.1 L5.2 R11.2
N23546308: C12.1 C13.1 FL15.2 L5.1 R11.1
N23546322: FL9.1 FL12.2
N23546328: FL11.2 FL12.1
N23546420: R67.2 R68.1 U3.14(EN/UVLO)
N23546459: R68.2 R69.1 U3.15(OVP)
N23546547: C136.1 U3.18(DVDT)
N23546577: R66.1 U3.17(ILIM)
N23546608: R61.1 U3.19(IMON)
N23546717: R57.2 U3.20(F\L\T\)
N23546802: FL3.1 L2.2 R5.2
N23546814: C2.1 C3.1 FL7.2 L2.1 R5.1
N23546828: FL1.1 FL4.2
N23546834: FL3.2 FL4.1
N23898061: R158.2 U21.1(STANDBY)
N24518728: C348.1 R196.2
N24522043: C501.1 R244.2
N24608149: D1.2 F2.2 TP37.1(TP)
N24763505: U35.6(PGATE) U36.4(GATE)
N24763516: D3.3(K) L30.1 U36.1(S1) U36.2(S2) U36.3(S3)
N24766225: R257.2 U35.2(RT)
N24772813: C523.2 R256.1 U35.1(ADJ)
N24774750: C522.1 U35.7(VCC)

Pads without a net: D1 1; J1 2 4 6 10 14 22 25 26 27 28 29 31 33 35 37 39; J20 1 2 3 4 6 8 10 14 18 20 22 30 32 34 36 38 40; U3 2; U4 2; U7 2; U8 2; U9 10 11 12 13 23 24 37 38 47 48 49 50 51 52 53 54 55 56 57 58; U12 2; U13 2; U16 2; U17 2; U18 2; U19 2; U22 10 20 21; U23 2; U24 10 11 12 13 17 18 19 20 21 22 23 24 25 26 27 28 37 38 47 48 49 50 51 52 53 54 55 56 57 58; U25 10 11 12 13 17 18 19 20 21 22 23 24 25 26 27 28 37 38 47 48 49 50 51 52 53 54 55 56 57 58; U26 2; U27 2; U32 22

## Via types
v1: diameter 0.457, hole 0.203, TOP to BOTTOM, 2713 vias

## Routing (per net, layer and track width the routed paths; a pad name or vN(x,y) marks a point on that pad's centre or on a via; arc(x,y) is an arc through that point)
DGND: length 342.5
  TOP w0.203: U30.6 v1(25.88,32.74) ; v1(73.03,153.29) 72.91,153.4 72.59,153.4 72.39,153.6 R2.1 ; U31.6 14.67,33 14.61,32.94 v1(14.61,32.51) ; U29.6 45.2,106.89 44.98,106.68 v1(44.98,106.25) ; v1(72.39,113.67) 72.39,113.67 R19.1
  TOP w0.254: v1(72.44,94.54) 72.39,94.59 R27.1 ; v1(12.28,58.12) 12.05,58.36 R43.2 ; R48.1 v1(72.39,35.86) ; R33.1 v1(72.39,74.97) ; R18.1 9.94,130.33 v1(9.78,130.48) ; v1(10.17,174.53) 9.94,174.3 R1.1 ; v1(24.23,31.34) 25.23,32.34 U30.6 ; v1(9.78,152.6) 9.94,152.44 R7.1 ; v1(72.47,133.2) 72.39,133.27 R8.1 ; R26.1 v1(9.94,107.78) ; R44.1 v1(72.39,55.42) ; R50.1 v1(72.39,16.3)
  TOP w0.305: J2.24 v1(46.09,38.22) ; v1(50.29,35.51) 50.59,35.81 J2.12 ; v1(49.56,92.07) 49.08,91.58 J1.24 ; v1(50.29,6.22) 50.99,6.22 R259.2 ; J2.16 v1(49.09,38.22) ; J1.12 v1(53.58,92.03) ; J1.16 v1(52.08,92.03)
  TOP w0.381: C86.2 v1(49.66,70.27) C446.2 ; C91.2 8.76,47.87 v1(8.72,47.84) ; C433.2 40.88,73.18 v1(40.83,73.23) ; v1(53.89,77.97) 54.14,78.21 C69.2 53.09,79.51 v1(52.91,79.32) ; R210.2 24.9,34.91 25.07,34.75 C364.2 v1(25.65,35.46) ; v1(36.48,126) C24.2 ; C418.2 19.91,47.89 v1(20.04,48.02) ; C309.2 22.76,52.92 v1(22.83,52.85) ; v1(7.09,47.82) 7.36,48.08 C109.2 ; C438.2 C255.2 31.9,60.15 v1(31.91,60.14) ; C332.2 v1(44.36,72.73) ; C465.2 27.63,112.43 v1(27.61,112.45) ; C411.2 6.33,59.71 v1(6.22,59.6) ; v1(42.22,72.88) 42.29,72.81 C437.2 ; v1(16.57,62.34) 16.96,62.73 C99.2 ; C331.2 v1(6.1,51.94) ; C98.2 7.89,63.39 v1(7.62,63.12) ; C356.2 41.34,110.23 v1(41.33,110.24) ; v1(13.22,60) 13.71,60.5 ; 13.71,60.5 13.71,60.45 v1(14.16,60) ; 13.71,60.5 R39.2 ; R36.2 44.23,68.56 v1(44.87,69.2) ; v1(22.39,119.68) 22.48,119.59 C145.2 ; C390.2 25.58,165.48 v1(25.37,165.28) ; v1(34.54,31.85) C115.2 v1(35.68,32.83) ; v1(18.26,66.83) 18.26,66.3 C324.2 ; C28.2 29.64,120.72 v1(30.13,120.23) ; C454.2 25.8,126.09 25.71,126.01 v1(25.71,125.86) 25.79,125.78 C450.2 ; C92.2 61,61.57 v1(60.87,61.71) ; C113.2 43.88,39.81 v1(43.57,40.12) ; v1(15.1,60) 15.18,60.08 C104.2 ; C427.2 12.44,62.38 v1(12.61,62.21) ; v1(40.19,92.89) C62.2 v1(41,93.64) ; C251.2 20.63,81.65 v1(20.61,81.67) ; C516.2 41.82,108.95 v1(41.45,108.58) ; v1(13.84,66.85) 13.84,66.4 C374.2 ; C469.2 40.31,119.22 v1(40.19,119.33) ; v1(32.08,112.7) 32.65,112.13 C187.2 ; v1(11.3,66.67) 10.95,66.32 C421.2 C422.2 ; C258.2 v1(32.8,71.43) 32.74,71.38 C83.2 ; v1(10.32,47.84) 10.32,48.52 C419.2 ; C387.2 37.14,162.66 v1(37.88,162.66) ; v1(31.32,78.97) 31.32,79.01 31.7,79.39 C70.2 ; v1(73.15,46.23) C112.2 ; C149.2 29.3,126.39 v1(29.08,126.17) 29.29,125.97 C456.2 ; C114.2 v1(39.74,39.13) ; C79.2 28.77,73.83 v1(29.65,73.83) ; v1(38.56,79.07) 38.56,79.19 38.36,79.39 C71.2 ; v1(15.8,66.85) 15.74,66.79 C372.2 ; C453.2 28.66,120.23 v1(29.2,120.23) ; C459.2 25.11,113.5 v1(26.15,113.5) ; C75.2 15.84,75.86 v1(16.39,76.41) ; C462.2 23.78,117.69 v1(23.94,117.85) ; C108.2 v1(67.33,53.13) ; C208.2 v1(31.79,106.7) ; v1(9.05,63.11) 9.05,63.1 9.64,63.1 9.91,63.37 C425.2 ; C141.2 25.44,112.48 v1(26.15,112.48) 26.35,112.29 C460.2 ; C371.2 29.02,122.66 v1(28.84,122.49) ; C272.2 49,67.87 v1(49.67,67.87) 49.69,67.89 C326.2 ; v1(40.99,115.62) 40.89,115.62 40.89,115.52 40.55,115.52 C195.2 ; R42.2 16.72,60.26 v1(16.98,60) ; C429.2 C424.2 17.65,62.89 17.4,63.14 C99.2 ; C441.2 C442.2 49.9,62.78 v1(50.52,63.4) ; v1(5.97,53.33) 6.08,53.44 C420.2 ; v1(34.57,168.55) 34.48,168.64 C409.2 ; C95.2 19.74,66.49 v1(19.74,66.8) ; C322.2 33.38,60.84 v1(33.38,60.14) ; C447.2 v1(49.53,59.09) C445.2 ; v1(73.2,26.7) 72.5,26.7 ; C66.2 v1(55.72,81.02) ; v1(31.07,120.23) 30.89,120.41 C30.2 ; C99.2 16.39,63.14 16.28,63.25 C426.2 ; v1(6.1,50.8) 6.19,50.7 C313.2 ; R222.1 v1(72.99,175.85) ; C59.2 v1(45.26,96.74) ; R232.2 32.8,159.35 v1(32.54,159.08) ; C81.2 63.11,68.13 v1(62.92,68.33) ; C117.2 v1(66.37,32.46) ; v1(43.9,66.2) 43.92,66.22 C367.2 ; C455.2 38.66,124.37 v1(38.66,125.44) ; v1(60.36,65.9) C87.2 ; v1(20.17,49.61) 20.17,49.56 19.79,49.18 C414.2 ; v1(37.6,72.84) 37.49,72.96 C317.2 36.09,72.96 v1(36.08,72.95) C82.2 ; v1(61.21,79.25) 61.33,79.37 C65.2 ; v1(15.52,48.69) 15.81,48.69 C415.2 ; R233.2 30.8,159.4 v1(30.71,159.31) ; C342.2 22.57,59.45 22.18,59.83 v1(22.18,59.94) ; C464.2 34.97,108.11 v1(34.59,108.48) ; C472.2 v1(37.63,169.74) ; v1(36.9,166.19) 37.12,166.41 C384.2 ; C106.2 v1(37.29,55.87) ; R35.2 53.88,74.34 v1(53.82,74.41) ; C78.2 v1(39.4,74.4) ; v1(47.4,33.66) 47.41,33.66 v1(50.02,33.66) ; R34.2 v1(52.32,74.75) ; C64.2 v1(66.67,81.66) ; C428.2 C94.2 20.83,65.85 v1(20.75,65.93) ; v1(46.14,60.59) 47.18,60.59 C103.2 ; C382.2 37.13,163.83 v1(37.79,163.83) ; C61.2 v1(47.71,94.86) ; v1(16.62,47.3) 16.58,47.26 C417.2 ; C93.2 v1(46.14,66.16) ; v1(45.44,62.41) C366.2 46.08,62.95 46.19,63.07 C368.2 ; v1(11.29,52.14) C416.2 11.29,49.12 11.78,48.63 v1(12.18,48.63) ; C358.2 v1(27.82,28.22) ; C440.2 43.4,55.52 v1(43.46,55.46) ; C63.2 61.02,84.97 v1(60.61,84.57) ; C470.2 v1(24.74,163.91)
  BOTTOM w0.203: v1(17.46,77.52) 16.21,76.27 U22.7 ; v1(17.46,78.6) 17.71,78.85 U22.16
  BOTTOM w0.229: v1(33.45,167.08) 33.18,167.36 U32.7
  BOTTOM w0.254: R239.2 v1(19.18,20.75) ; R198.2 v1(42.04,16.43) ; C510.2 34.31,88.86 v1(34.44,88.72) ; C257.2 35.64,72.95 v1(36.08,72.95) ; v1(17.61,22.18) 17.75,22.04 U33.4 19.04,22.04 v1(19.33,22.33) 19.12,22.54 U33.3 17.25,22.54 U33.17
  BOTTOM w0.305: v1(6.12,97.27) 5.86,97.54 U16.3 ; v1(76.96,164.16) 77.22,163.89 U4.3 ; U7.1 4.86,140.12 v1(5.11,139.87) ; v1(77.97,28.02) 78.22,27.77 U27.1 ; U16.1 4.86,97.53 v1(5.11,97.27) ; U22.19 19.72,78.77 20.61,79.66 C252.2 v1(20.61,81.67) ; J20.24 39.26,184.1 v1(38.64,184.71) ; v1(48.77,6.22) 48.03,6.22 47.92,6.11 47.33,6.11 ; v1(5.07,162.26) 4.86,162.04 U3.16 ; U18.1 78.22,85.37 v1(77.97,85.63) ; v1(5.08,96.23) 4.86,96.01 U16.16 ; v1(76.96,144.53) 77.22,144.26 U8.3 ; v1(77.97,46.87) 78.22,46.62 U26.1 ; v1(76.96,85.63) 77.22,85.36 U18.3 ; U13.3 77.22,124.22 v1(76.96,124.49) ; v1(77.97,124.49) 78.22,124.24 U13.1 ; U23.16 78.22,67.59 v1(78,67.36) ; U4.16 78.22,165.43 v1(78,165.2) ; v1(77.97,144.53) 78.22,144.28 U8.1 ; v1(6.11,163.3) 5.86,163.56 U3.3 ; v1(77.97,164.16) 78.22,163.91 U4.1 ; v1(76.96,104.94) 77.22,104.67 U17.3 ; v1(77.97,66.32) 78.22,66.07 U23.1 ; U7.16 4.86,138.6 v1(5.08,138.83) ; U17.1 78.22,104.69 v1(77.97,104.94) ; U12.1 4.86,119.19 v1(5.11,118.94) ; U3.1 4.86,163.54 v1(5.1,163.3) ; U13.16 78.22,125.75 v1(78,125.53) ; v1(78,47.91) 78.22,48.14 U26.16 ; J20.16 42.25,184.16 v1(41.72,184.7) ; v1(16.92,72.69) 17.01,72.69 17.32,73 17.32,74.24 17.21,74.34 U22.4 ; U27.3 77.22,27.75 v1(76.96,28.02) ; v1(20.16,73.32) 19.84,73.64 C474.2 19.4,74.57 18.71,75.26 U22.1 ; U35.4 50.29,7.09 v1(50.29,6.22) ; U17.16 78.22,106.21 v1(78,105.98) ; v1(6.12,118.94) 5.86,119.21 U12.3 ; v1(78,86.67) 78.22,86.89 U18.16 ; U8.16 78.22,145.79 v1(78,145.57) ; v1(43.31,184.6) 43.42,184.6 43.75,184.26 J20.12 ; U23.3 77.22,66.05 v1(76.96,66.32) ; C344.2 42.33,22.19 42,21.86 U28.3 ; v1(78,29.06) 78.22,29.28 U27.16 ; U7.3 5.86,140.14 v1(6.12,139.87) ; U12.16 4.86,117.67 v1(5.08,117.9) ; U26.3 77.22,46.61 v1(76.96,46.87)
  BOTTOM w0.381: v1(23.07,109.63) 23.07,109.99 23.38,110.3 C206.2 ; C282.2 9.72,65.92 v1(9.52,66.12) ; C254.2 43.98,72.73 v1(44.36,72.73) ; C339.2 v1(81.79,28.82) ; U20.4 v1(14.13,88.83) ; v1(26.6,50.2) 26.68,50.13 C318.2 ; C327.2 26.65,41.54 v1(26.58,41.61) ; v1(28.3,146.44) C147.2 v1(28.96,145.5) ; v1(30.8,128.43) R88.2 ; C430.2 28,50.07 v1(27.87,50.2) ; C174.2 v1(29.08,126.17) ; C163.2 v1(74.58,149.16) ; R61.2 v1(1.28,164.06) ; C316.2 19.79,50.05 20.17,49.67 v1(20.17,49.61) 20.17,49.53 19.68,49.03 C321.2 ; v1(23.66,114.86) 23.69,114.83 C196.2 ; C370.2 v1(32,125.68) ; C233.2 v1(81.79,86.43) ; R136.2 v1(1.28,95.14) ; v1(7.91,37.39) 7.84,37.47 7.84,38.03 C330.2 ; R203.1 44.86,53.2 45.24,53.58 v1(45.24,53.87) 45.24,54.14 44.86,54.52 R202.1 ; R130.2 v1(81.79,88.98) ; C110.2 6.44,57.68 v1(6.33,57.57) ; C228.2 v1(74.33,90.25) ; R115.2 v1(1.28,115.59) ; C303.2 v1(74.33,51.5) ; v1(16.66,82.2) 16.66,82.11 C242.2 ; v1(26.24,164.81) 26.24,164.63 C399.2 ; R70.2 v1(81.79,163.44) ; v1(13.11,20.73) 13.44,20.39 C500.2 ; C263.2 v1(33.02,70.08) ; C312.2 v1(81.79,47.67) ; v1(34.59,108.48) 34.77,108.31 C204.2 ; v1(49.66,70.27) 49.23,70.27 C261.2 ; v1(25.71,125.86) 25.71,125.38 C23.2 ; C225.2 v1(74.33,109.57) ; v1(32.91,148.34) C144.2 v1(31.81,149.19) ; R116.2 v1(81.79,123.76) ; C280.2 v1(50.55,65.11) ; C152.2 v1(30.29,139.02) ; C423.2 16.66,42.63 v1(15.81,42.63) ; v1(27.8,45.98) 27.75,45.93 27.75,45.09 ; v1(36.54,56.59) C302.2 ; v1(40.99,115.62) 40.43,115.62 40.36,115.69 39.83,115.69 C191.2 ; v1(29.17,147.86) C184.2 v1(29.17,146.41) ; v1(22.18,59.94) 22.52,59.6 C295.2 ; v1(50.52,63.4) 50.42,63.3 C287.2 ; v1(27.85,37.37) 27.8,37.32 C304.2 ; C323.2 26.6,45.91 v1(26.53,45.98) ; R106.2 v1(1.28,119.66) ; v1(22.1,44.73) 21.47,44.73 v1(21.47,44.74) 21.43,44.78 v1(20.88,44.78) 20.91,44.8 C294.2 ; R147.2 R148.2 v1(11.59,94.24) ; C392.2 v1(25.83,161.93) ; R81.2 v1(1.28,140.59) ; R65.2 v1(81.9,166.3) ; R141.2 v1(81.79,84.9) ; C329.2 10.94,41.03 v1(10.7,41.26) ; R162.2 v1(81.79,69.67) ; C400.2 26.14,163.07 v1(26.01,162.94) ; R62.2 v1(81.79,167.51) ; v1(8.19,84.87) 8.3,84.76 C241.2 ; C407.2 v1(38.84,166.91) ; v1(6.22,59.6) 6.44,59.82 C293.2 ; C214.2 v1(8.75,114.31) ; C386.2 37.12,167.52 v1(38.1,167.52) ; C164.2 v1(1.28,139.07) ; R95.2 v1(81.79,143.8) ; R204.1 v1(41.51,120.52) ; R194.2 v1(81.79,27.29) ; R108.2 v1(81.79,127.84) ; C291.2 v1(42.22,72.88) ; v1(11.49,79.51) 11.1,79.51 11,79.41 arc(10.8,79.11) U21.2 ; C209.2 v1(74.33,129.12) ; R129.2 v1(81.77,106.95) ; C275.2 20.18,65.93 v1(20.75,65.93) ; C173.2 35.9,126 v1(36.48,126) ; v1(32.8,71.43) 32.8,71.06 C85.2 ; R187.2 v1(81.79,46.15) ; v1(32.3,143.38) C148.2 v1(31.56,144.13) ; v1(12.37,66.83) 12.32,66.78 C97.2 ; C310.2 v1(22.83,52.85) ; C443.2 27.85,40.76 v1(27.85,41.61) ; C345.2 v1(39.73,18.27) ; R189.2 v1(81.79,31.37) ; C185.2 40.15,119.38 v1(40.19,119.33) ; v1(65.88,155.7) 65.94,155.76 R52.2 ; C135.2 v1(74.33,168.79) ; 43.22,22.19 43.97,22.94 ; C210.2 v1(1.28,118.14) ; C253.2 v1(81.79,67.12) ; R184.2 v1(81.79,49.02) ; C170.2 v1(81.79,145.33) ; R181.2 v1(81.79,50.23) ; 26.24,109.22 v1(26.24,108.05) ; C234.2 v1(8.75,92.65) ; v1(17.5,66.62) 17.5,66.02 C278.2 ; C245.2 10.78,75.44 ; R90.2 v1(1.28,137.73) ; C290.2 v1(33.38,60.14) ; C333.2 26.65,37.3 v1(26.58,37.37) ; C319.2 v1(10.32,47.84) ; R69.2 v1(1.28,159.99) ; 6.69,37.44 v1(6.64,37.39) 6.64,38.22 C410.2 ; v1(49.53,59.09) 49.44,59.18 C296.2 ; R140.2 v1(1.28,93.92) ; C373.2 15.54,65.89 15.34,65.89 v1(15.01,66.22) 14.41,66.22 13.97,65.77 C101.2 ; R192.2 v1(81.79,30.16) ; R128.2 v1(1.28,98) ; C311.2 v1(5.97,53.33) ; C231.2 v1(1.28,96.47) ; v1(10.75,42.48) 10.88,42.35 C412.2 ; C89.2 8.89,48.01 v1(8.72,47.84) ; v1(49.67,67.87) 49.43,67.64 C273.2 ; R137.2 v1(81.77,104.09) ; R168.2 v1(81.79,65.6) ; R111.2 v1(81.9,126.63) ; R125.2 v1(81.67,108.17) ; R89.2 v1(81.9,146.67) ; R83.2 v1(81.79,147.88) ; C139.2 v1(81.79,164.96) ; C136.2 v1(1.28,162.54) ; v1(36.9,166.19) C383.2 ; R152.2 v1(7.91,88.45) ; R135.2 v1(81.79,87.77) ; C230.2 v1(81.77,105.61) ; C336.2 v1(74.33,32.65) ; C213.2 v1(81.79,125.29) ; C102.2 v1(31.91,60.14) ; 15.83,41.48 15.83,41.48 16.04,41.28 C328.2 ; R166.2 v1(81.79,68.47) ; C177.2 22.28,112.35 v1(22.28,112.8) ; v1(43.46,55.46) C301.2 ; R112.2 v1(1.28,116.82) ; C244.2 v1(74.33,70.95) ; R205.1 v1(42.5,120.52) ; v1(37.88,162.66) C398.2 ; R66.2 v1(1.28,161.2) ; C279.2 v1(6.1,51.94) ; C186.2 v1(23.31,117) ; v1(37.79,163.83) C381.2 ; C385.2 v1(37.74,168.87) ; R93.2 v1(1.28,136.52) ; C176.2 v1(8.75,135.26)
  vias: v1(2.67,31.85) v1(2.67,29.95) v1(2.93,144.42) v1(2.93,14.18) v1(3.01,155.76) v1(3.01,123.26) v1(3.47,112.37) v1(3.85,151.9) v1(3.9,149.09) v1(3.93,107.71) v1(3.86,104.9) v1(4.01,171.19) v1(4,133.38) v1(3.99,129.8) v1(3.95,127) v1(4.08,178.59) v1(4.07,173.99) v1(4.46,147.08) v1(4.76,125.77) v1(5.29,155.68) v1(5.4,167.6) v1(5.76,151.9) v1(5.8,149.09) v1(5.84,107.71) v1(5.77,104.9) v1(5.91,171.19) v1(5.9,129.8) v1(5.86,127) v1(5.97,173.99) v1(6.09,162.26) v1(6.1,138.83) v1(6.1,117.9) v1(6.1,96.23) v1(6.2,56.18) v1(6.42,167.6) v1(6.42,145.26) v1(6.38,123.22) v1(6.37,101.18) v1(6.96,96.32) v1(7.13,163.3) v1(7.11,162.26) v1(7.14,139.87) v1(7.11,138.83) v1(7.14,118.94) v1(7.11,117.9) v1(7.14,97.27) v1(7.12,13.95) v1(7.27,37.39) v1(7.73,111.15) v1(8.03,174.01) v1(8.02,149.11) v1(7.97,104.9) v1(8.1,171.19) v1(8.08,151.89) v1(8.11,129.81) v1(8.11,127.01) v1(8.23,107.71) v1(8.37,158.35) v1(8.64,132.62) v1(8.69,68.2) v1(8.8,156.14) v1(9.23,151.91) v1(9.19,129.8) v1(9.24,104.9) v1(9.28,174) v1(9.33,171.19) v1(9.33,149.1) v1(9.33,127) v1(9.31,70.09) v1(9.27,27.56) v1(9.38,158.35) v1(9.37,108.92) v1(9.39,80.21) v1(9.36,73.93) v1(9.38,71.9) v1(9.4,26.54) v1(9.53,66.83) v1(9.8,82.06) v1(9.91,15.88) v1(9.91,14.86) v1(9.91,13.84) v1(9.91,12.83) v1(9.91,11.81) v1(9.99,54.49) v1(10.03,28.19) v1(10.16,37.31) v1(10.54,88.47) v1(10.62,178.52) v1(10.55,3.92) v1(10.72,108.35) v1(10.7,83.19) v1(10.71,41.89) v1(10.81,152.81) v1(10.84,130.7) v1(10.86,56.67) v1(10.91,47.23) v1(10.92,30.99) v1(10.92,30.1) v1(10.92,29.21) v1(10.92,28.32) v1(11,174.42) v1(11,154.54) v1(10.98,81.46) v1(10.99,75.5) v1(10.98,73.67) v1(10.98,71.7) v1(11.01,70.06) v1(10.99,60.24) v1(11.2,95.6) v1(11.19,76.27) v1(11.19,74.55) v1(11.3,37.31) v1(11.4,72.51) v1(11.69,156.82) v1(11.66,108.2) v1(11.68,15.88) v1(11.68,14.86) v1(11.68,13.84) v1(11.68,12.83) v1(11.68,11.81) v1(11.76,173.82) v1(11.83,129.7) v1(11.79,114.6) v1(11.77,113.57) v1(11.92,135.42) v1(11.87,134.51) v1(12.01,151.71) v1(12.04,150) v1(12.02,82.5) v1(11.97,70.98) v1(12.12,172.12) v1(12.14,105.77) v1(12.08,47.28) v1(12.16,80.33) v1(12.22,69.52) v1(12.28,59.06) v1(12.28,57.19) v1(12.28,56.25) v1(12.28,55.31) v1(12.44,117.4) v1(12.53,127.95) v1(12.53,95.33) v1(12.53,52.94) v1(12.66,94.42) v1(12.7,32.51) v1(12.82,138.88) v1(12.84,10.78) v1(12.89,161.68) v1(12.92,107.55) v1(13.13,132.48) v1(13.14,48.65) v1(13.22,59.06) v1(13.22,58.12) v1(13.22,57.19) v1(13.22,56.25) v1(13.22,55.31) v1(13.22,54.37) v1(13.3,173.8) v1(13.28,129.63) v1(13.34,81.48) v1(13.27,47.28) v1(13.34,18.37) v1(13.42,150.04) v1(13.37,105.81) v1(13.39,78.91) v1(13.59,37.31) v1(13.71,137.68) v1(13.73,71.73) v1(13.69,69.57) v1(13.72,32.54) v1(13.83,151.73) v1(13.79,84.29) v1(13.91,127.95) v1(14.06,70.49) v1(14.08,52.47) v1(14.21,107.55) v1(14.19,79.73) v1(14.16,59.06) v1(14.16,58.12) v1(14.16,57.19) v1(14.16,56.25) v1(14.16,55.31) v1(14.16,54.37) v1(14.18,47.23) v1(14.22,17.61) v1(14.39,172.15) v1(14.46,114.98) v1(14.46,113.97) v1(14.46,112.95) v1(14.58,48.69) v1(14.69,173.79) v1(14.75,137.64) v1(14.73,73.75) v1(14.73,37.31) v1(14.81,154.77) v1(14.83,68.12) v1(14.99,150.04) v1(15.02,135.67) v1(15.02,134.66) v1(15.02,133.64) v1(14.97,129.62) v1(15.01,105.84) v1(15.07,87.44) v1(15.1,83.27) v1(15.1,59.06) v1(15.1,58.12) v1(15.1,57.19) v1(15.1,56.25) v1(15.1,55.31) v1(15.1,54.37) v1(15.11,17.61) v1(15.28,127.88) v1(15.33,85.8) v1(15.47,114.98) v1(15.47,113.97) v1(15.47,112.95) v1(15.48,16.83) v1(15.62,151.68) v1(15.63,70.12) v1(15.56,47.3) v1(15.8,138.77) v1(15.77,116.6) v1(15.76,42.05) v1(15.76,41.41) v1(15.9,172.09) v1(15.86,160.89) v1(15.86,159.88) v1(15.86,158.86) v1(15.86,157.85) v1(15.88,107.35) v1(15.93,104.78) v1(15.9,93.63) v1(15.9,91.72) v1(16.04,135.67) v1(16.04,134.66) v1(16.04,133.64) v1(15.95,90.99) v1(15.95,89.08) v1(15.95,87.18) v1(16.04,60) v1(16.04,59.06) v1(16.04,58.12) v1(16.04,57.19) v1(16.04,56.25) v1(16.04,55.31) v1(16.04,54.37) v1(16.06,149.94) v1(16.09,110.01) v1(16.21,123.64) v1(16.33,23.42) v1(16.33,22.81) v1(16.33,22.2) v1(16.3,16.83) v1(16.41,84.59) v1(16.37,78.6) v1(16.37,77.52) v1(16.52,173.66) v1(16.58,126.87) v1(16.68,125.41) v1(16.69,122.31) v1(16.7,120.29) v1(16.7,118.07) v1(16.68,116.41) v1(16.67,114.54) v1(16.69,112.6) v1(16.68,108.59) v1(16.83,149.23) v1(16.88,160.89) v1(16.88,159.88) v1(16.88,158.86) v1(16.88,157.85) v1(16.9,151.38) v1(16.88,129.11) v1(16.94,22.81) v1(16.98,171.59) v1(17,147.9) v1(17,146) v1(17,144.09) v1(17,142.19) v1(17,140.28) v1(17,138.38) v1(17,136.47) v1(16.98,133.55) v1(16.98,59.06) v1(16.98,58.12) v1(16.98,57.19) v1(16.98,56.25) v1(16.98,55.31) v1(16.98,54.37) v1(17,23.39) v1(17,22.18) v1(17.1,106.31) v1(17.25,29.72) v1(17.25,28.96) v1(17.27,69.49) v1(17.37,31.37) v1(17.37,30.58) v1(17.53,130.45) v1(17.5,107.65) v1(17.47,86.26) v1(17.49,76.41) v1(17.63,104.83) v1(17.63,102.92) v1(17.63,101.02) v1(17.63,98.73) v1(17.63,97.21) v1(17.63,95.3) v1(17.63,93.4) v1(17.63,91.49) v1(17.63,88.42) v1(17.64,70.52) v1(17.61,23.39) v1(17.61,22.79) v1(17.72,128.62) v1(17.72,33.56) v1(17.72,32.78) v1(17.82,170.77) v1(17.93,177.07) v1(17.85,173.09) v1(17.92,59.06) v1(17.92,58.12) v1(17.92,57.19) v1(17.92,56.25) v1(17.92,55.31) v1(18,150.45) v1(18.07,70.12) v1(18.24,129.56) v1(18.33,124.25) v1(18.33,114.21) v1(18.35,121.83) v1(18.35,119.93) v1(18.35,118.02) v1(18.35,116.12) v1(18.41,112.08) v1(18.53,169.75) v1(18.53,33.56) v1(18.53,32.78) v1(18.54,3.68) v1(18.54,2.79) v1(18.54,1.91) v1(18.64,168.47) v1(18.64,166.56) v1(18.64,164.66) v1(18.64,162.75) v1(18.64,160.85) v1(18.64,158.94) v1(18.64,157.04) v1(18.64,155.13) v1(18.64,153.23) v1(18.64,151.32) v1(18.64,149.42) v1(18.64,147.51) v1(18.64,145.61) v1(18.64,143.7) v1(18.64,141.8) v1(18.64,139.89) v1(18.64,137.99) v1(18.64,136.08) v1(18.55,78.6) v1(18.56,77.52) v1(18.58,76.41) v1(18.78,83.82) v1(18.92,85.22) v1(18.94,60.46) v1(18.98,110.37) v1(19.1,171.84) v1(19.07,133.45) v1(19.26,108.37) v1(19.26,106.47) v1(19.26,104.56) v1(19.26,102.66) v1(19.28,101.12) v1(19.26,98.85) v1(19.26,96.94) v1(19.26,95.04) v1(19.26,93.13) v1(19.26,91.23) v1(19.27,89.21) v1(19.26,87.27) v1(19.31,75.58) v1(19.43,3.68) v1(19.43,2.79) v1(19.43,1.91) v1(19.71,69.55) v1(19.85,131.64) v1(19.82,72.78) v1(19.99,129.28) v1(20.01,127.89) v1(20,124.85) v1(19.99,121.05) v1(19.99,119.31) v1(19.99,117.51) v1(19.98,115.86) v1(19.99,114.7) v1(20.02,113.03) v1(20.07,170.27) v1(20.08,70.52) v1(20.27,168.25) v1(20.27,166.35) v1(20.27,164.44) v1(20.27,162.54) v1(20.27,160.63) v1(20.27,158.73) v1(20.27,156.82) v1(20.27,154.92) v1(20.27,153.01) v1(20.27,151.11) v1(20.27,149.2) v1(20.27,147.3) v1(20.27,145.39) v1(20.27,143.49) v1(20.27,141.58) v1(20.27,139.68) v1(20.27,137.77) v1(20.27,135.87) v1(20.32,3.68) v1(20.32,2.79) v1(20.32,1.91) v1(20.57,143.33) v1(20.76,70.59) v1(20.91,111.42) v1(20.9,108.94) v1(20.9,107.04) v1(20.9,105.13) v1(20.9,103.23) v1(20.9,101.32) v1(20.9,99.42) v1(20.9,97.51) v1(20.9,95.61) v1(20.9,93.7) v1(20.9,91.8) v1(20.9,89.89) v1(20.94,88.02) v1(20.9,85.15) v1(20.93,83.93) v1(20.91,71.41) v1(21.1,69.92) v1(21.21,3.68) v1(21.21,2.79) v1(21.21,1.91) v1(21.3,143.29) v1(21.51,86.64) v1(21.53,70.85) v1(21.5,34.93) v1(21.5,34.12) v1(21.64,120.58) v1(21.56,30.63) v1(21.65,130.84) v1(21.66,129.2) v1(21.66,128.19) v1(21.67,124.86) v1(21.82,115.96) v1(21.82,80.03) v1(22.04,116.95) v1(22,114.96) v1(21.96,78.04) v1(22.03,76.2) v1(22.1,3.68) v1(22.1,2.79) v1(22.1,1.91) v1(22.23,85.85) v1(22.23,83.94) v1(22.23,82.04) v1(22.36,149.77) v1(22.36,149.13) v1(22.65,171.21) v1(22.72,91.47) v1(22.72,89.57) v1(22.89,108.65) v1(22.87,107.09) v1(22.87,105.19) v1(22.85,101.01) v1(22.85,99.1) v1(22.85,97.2) v1(22.85,95.29) v1(22.85,93.39) v1(23.04,104.11) v1(22.99,3.68) v1(22.99,2.79) v1(22.99,1.91) v1(23.44,31.34) v1(23.37,20.57) v1(23.64,161.01) v1(23.64,150.51) v1(23.61,115.84) v1(23.79,156.75) v1(23.76,86.79) v1(24.02,177.53) v1(23.96,85.87) v1(24.01,82.98) v1(23.96,81.49) v1(24.17,180.12) v1(24.46,61.2) v1(24.74,174.44) v1(24.86,143.96) v1(25.02,31.34) v1(25.42,169.83) v1(25.42,134.9) v1(25.46,171.98) v1(25.77,155.53) v1(25.81,138.23) v1(26.07,159.03) v1(26.2,60.56) v1(26.4,129.22) v1(26.48,115.84) v1(26.46,114.85) v1(26.61,178.78) v1(26.65,133.24) v1(26.68,183.92) v1(26.72,127.56) v1(26.86,137.44) v1(26.89,136.38) v1(27,149.98) v1(26.98,134.29) v1(27.14,116.94) v1(27.18,175.57) v1(27.24,50.2) v1(27.16,45.98) v1(27.21,41.61) v1(27.21,37.37) v1(27.32,174.08) v1(27.32,120.17) v1(27.38,171.93) v1(27.57,54.95) v1(27.75,137.12) v1(27.94,106.29) v1(27.87,60.21) v1(27.99,149.98) v1(27.95,56.42) v1(28.33,135.64) v1(28.26,119.29) v1(28.26,118.35) v1(28.26,117.41) v1(28.26,116.47) v1(28.26,115.53) v1(28.35,88.11) v1(28.42,128.52) v1(28.47,180.97) v1(28.47,129.1) v1(28.58,69.75) v1(28.59,68.99) v1(28.8,137.15) v1(28.85,133.24) v1(29.04,176.84) v1(28.99,168.56) v1(29.05,128.43) v1(29.19,147) v1(29.2,119.29) v1(29.2,118.35) v1(29.2,117.41) v1(29.2,116.47) v1(29.2,115.53) v1(29.2,114.59) v1(29.25,82.15) v1(29.25,81.01) v1(29.22,64.32) v1(29.27,170.65) v1(29.27,129.62) v1(29.28,108.09) v1(29.63,138.6) v1(29.64,89.38) v1(29.66,137.54) v1(29.68,136.99) v1(29.69,90.75) v1(29.67,90.07) v1(29.69,77.15) v1(29.83,133.11) v1(29.97,88.77) v1(30.14,134.53) v1(30.13,119.29) v1(30.13,118.35) v1(30.13,117.41) v1(30.13,116.47) v1(30.13,115.53) v1(30.13,114.59) v1(30.08,66.3) v1(30.08,65.39) v1(30.21,68.79) v1(30.21,67.85) v1(30.29,104.42) v1(30.33,89.36) v1(30.35,183.51) v1(30.41,167.08) v1(30.41,166.07) v1(30.41,165.05) v1(30.41,164.04) v1(30.36,102.41) v1(30.38,90.73) v1(30.35,90.04) v1(30.53,155.47) v1(30.58,127.36) v1(30.62,74.31) v1(30.56,73.34) v1(30.67,186.18) v1(30.82,64.75) v1(30.82,62.57) v1(30.94,134.89) v1(31.02,138.34) v1(31.07,119.29) v1(31.07,118.35) v1(31.07,117.41) v1(31.07,116.47) v1(31.07,115.53) v1(31.07,114.59) v1(31.19,152.93) v1(31.42,167.08) v1(31.42,166.07) v1(31.42,165.05) v1(31.42,164.04) v1(31.52,135.89) v1(31.56,186.18) v1(31.62,122.56) v1(31.72,133.12) v1(31.93,185.06) v1(32.01,120.23) v1(32.01,119.29) v1(32.01,118.35) v1(32.01,117.41) v1(32.01,116.47) v1(32.01,115.53) v1(32.01,114.59) v1(31.98,67.69) v1(31.99,65.11) v1(31.99,64.22) v1(32.08,171.6) v1(32.11,155.5) v1(32.08,129.67) v1(32.15,72.41) v1(32.15,70.89) v1(32.21,69.13) v1(32.28,187.43) v1(32.34,131.12) v1(32.32,129.22) v1(32.45,186.18) v1(32.36,173.69) v1(32.44,167.08) v1(32.44,166.07) v1(32.44,165.05) v1(32.44,164.04) v1(32.36,133.82) v1(32.58,139.37) v1(32.61,135.64) v1(32.58,60.14) v1(32.64,16.68) v1(32.64,15.88) v1(32.75,188.32) v1(32.83,137.22) v1(32.97,152.93) v1(32.95,120.23) v1(32.95,119.29) v1(32.95,118.35) v1(32.95,117.41) v1(32.95,116.47) v1(32.95,115.53) v1(32.95,114.59) v1(33.21,66.53) v1(33.23,55.13) v1(33.23,50.15) v1(33.36,132.25) v1(33.45,166.07) v1(33.45,165.05) v1(33.45,164.04) v1(33.63,185.14) v1(33.55,122.53) v1(33.75,127.44) v1(33.81,130.2) v1(33.82,125.82) v1(33.89,128.92) v1(33.89,119.29) v1(33.89,118.35) v1(33.89,117.41) v1(33.89,116.47) v1(33.89,115.53) v1(34.14,186.23) v1(34.24,134.08) v1(34.2,35.85) v1(34.15,15.79) v1(34.25,188.32) v1(34.54,156.57) v1(34.53,135.71) v1(34.59,152.93) v1(34.55,104.39) v1(34.69,133.08) v1(34.78,137.93) v1(34.76,130.25) v1(34.85,139.6) v1(34.97,15.79) v1(35.31,13.59) v1(35.31,12.7) v1(35.31,11.81) v1(35.31,10.92) v1(35.31,10.03) v1(35.31,9.14) v1(35.41,129.61) v1(35.38,127.56) v1(35.53,118.19) v1(35.56,186.18) v1(35.57,120.5) v1(35.7,34.73) v1(35.7,33.94) v1(35.75,188.32) v1(36.02,127.27) v1(36.15,134.08) v1(36.25,156.18) v1(36.25,154.28) v1(36.2,13.59) v1(36.2,12.7) v1(36.2,11.81) v1(36.2,10.92) v1(36.2,10.03) v1(36.2,9.14) v1(36.36,138.17) v1(36.43,135.71) v1(36.41,52.54) v1(36.41,34.73) v1(36.41,33.94) v1(36.45,16) v1(36.49,133.38) v1(36.46,48.8) v1(36.55,139.99) v1(36.65,148.87) v1(36.83,181.58) v1(36.82,44.82) v1(37.21,186.18) v1(37.36,151.18) v1(37.38,33.66) v1(37.4,26.59) v1(37.53,179.96) v1(37.47,29.48) v1(37.57,108.69) v1(37.72,146.69) v1(37.77,159.99) v1(37.77,156.18) v1(37.77,154.28) v1(37.85,106.78) v1(37.92,141.02) v1(37.97,138.9) v1(38.05,134.08) v1(38.14,88.07) v1(38.08,82.9) v1(38.15,164.31) v1(38.25,132.57) v1(38.24,130.84) v1(38.24,100.49) v1(38.24,99.68) v1(38.34,135.71) v1(38.26,66.2) v1(38.26,65.26) v1(38.26,64.32) v1(38.26,63.38) v1(38.26,62.44) v1(38.5,73.57) v1(38.61,186.18) v1(38.56,113.84) v1(38.71,151.99) v1(38.73,149) v1(38.75,188.32) v1(38.89,110.24) v1(38.89,106.78) v1(38.9,82.92) v1(38.91,22.12) v1(38.91,21.34) v1(38.89,20.6) v1(39.02,100.49) v1(39.02,99.68) v1(39.17,181.53) v1(39.18,139.9) v1(39.2,67.14) v1(39.2,66.2) v1(39.2,65.26) v1(39.2,64.32) v1(39.2,63.38) v1(39.2,62.44) v1(39.2,61.5) v1(39.27,145.34) v1(39.25,28.81) v1(39.39,171.08) v1(39.4,142.46) v1(39.41,33.66) v1(39.6,78.53) v1(39.67,173.16) v1(39.73,163.45) v1(39.75,76.63) v1(39.7,22.12) v1(39.7,21.34) v1(39.7,20.6) v1(39.73,16.96) v1(39.73,16.14) v1(39.9,166.64) v1(39.85,112.19) v1(39.91,82.92) v1(40.01,184.53) v1(39.96,134.08) v1(40.13,186.18) v1(40.06,161.9) v1(40.06,159.99) v1(40.06,158.09) v1(40.06,156.18) v1(40.06,154.28) v1(40.06,152.37) v1(40.06,150.47) v1(40.14,132.51) v1(40.13,130.82) v1(40.11,110.59) v1(40.14,67.14) v1(40.14,66.2) v1(40.14,65.26) v1(40.14,64.32) v1(40.14,63.38) v1(40.14,62.44) v1(40.14,61.5) v1(40.24,135.71) v1(40.16,106.05) v1(40.25,188.32) v1(40.28,148.03) v1(40.26,13.59) v1(40.26,12.7) v1(40.26,11.81) v1(40.45,141.15) v1(40.41,113) v1(40.37,87.33) v1(40.44,22.12) v1(40.44,21.34) v1(40.44,20.6) v1(40.69,176.84) v1(40.75,143.81) v1(40.92,32.84) v1(40.86,26.65) v1(41.07,146.33) v1(41.08,67.14) v1(41.08,66.2) v1(41.08,65.26) v1(41.08,64.32) v1(41.08,63.38) v1(41.08,62.44) v1(41.08,61.5) v1(41.22,178.52) v1(41.25,165.81) v1(41.3,164.31) v1(41.29,28.48) v1(41.44,130.46) v1(41.4,77.75) v1(41.53,137.97) v1(41.58,161.95) v1(41.58,159.99) v1(41.58,158.09) v1(41.58,156.18) v1(41.58,154.28) v1(41.58,152.37) v1(41.58,150.47) v1(41.59,126.61) v1(41.73,186.18) v1(41.66,106.07) v1(41.75,188.32) v1(41.78,148.34) v1(41.79,142.49) v1(41.86,134.08) v1(41.86,113.06) v1(41.91,23.37) v1(41.98,174.67) v1(42.05,132.51) v1(42.01,111.53) v1(42.02,67.14) v1(42.02,66.2) v1(42.02,65.26) v1(42.02,64.32) v1(42.02,63.38) v1(42.02,62.44) v1(42.02,61.5) v1(42.04,14.48) v1(42.09,145.16) v1(42.09,140.59) v1(42.15,135.71) v1(42.27,180.31) v1(42.4,87.33) v1(42.4,33.66) v1(42.47,178.13) v1(42.46,163.94) v1(42.49,123.29) v1(42.63,100.26) v1(42.67,175.69) v1(42.67,173.79) v1(42.67,171.88) v1(42.67,169.98) v1(42.67,168.07) v1(42.67,166.17) v1(42.67,23.37) v1(42.86,28.51) v1(42.93,24.89) v1(42.89,16.45) v1(43.05,146.5) v1(42.96,67.14) v1(42.96,66.2) v1(42.96,65.26) v1(42.96,64.32) v1(42.96,63.38) v1(42.96,62.44) v1(42.96,61.5) v1(42.96,32.27) v1(43.14,143.84) v1(43.14,127.46) v1(43.05,24.13) v1(43.18,186.18) v1(43.25,188.32) v1(43.27,153.65) v1(43.27,151.74) v1(43.27,149.84) v1(43.27,147.93) v1(43.41,106.25) v1(43.42,100.26) v1(43.43,23.37) v1(43.43,18.03) v1(43.54,140.59) v1(43.51,137.97) v1(43.5,128.94) v1(43.6,27.8) v1(43.66,179.27) v1(43.69,155.51) v1(43.67,33.66) v1(43.72,28.51) v1(43.69,24.59) v1(43.7,16.45) v1(43.84,161.95) v1(43.84,159.99) v1(43.84,158.09) v1(43.84,156.18) v1(43.77,134.08) v1(43.76,132.51) v1(43.8,130.88) v1(43.81,13.59) v1(43.81,12.7) v1(43.81,11.81) v1(43.9,65.26) v1(43.9,64.32) v1(43.9,63.38) v1(43.9,62.44) v1(44.11,177.26) v1(44.05,135.71) v1(44.07,23.88) v1(44.25,175.69) v1(44.25,173.79) v1(44.25,171.88) v1(44.25,169.98) v1(44.25,168.07) v1(44.25,166.17) v1(44.19,114.05) v1(44.2,106.25) v1(44.21,100.26) v1(44.27,123.96) v1(44.26,40.32) v1(44.33,31.86) v1(44.4,164.39) v1(44.38,32.93) v1(44.49,145.19) v1(44.47,81.01) v1(44.48,52.43) v1(44.53,24.59) v1(44.52,16.45) v1(44.45,15.62) v1(44.58,130.44) v1(44.62,87.33) v1(44.72,157.11) v1(44.75,188.32) v1(44.87,170.98) v1(44.91,153.48) v1(44.91,151.57) v1(44.91,149.67) v1(44.95,148.09) v1(45.01,184.7) v1(45.01,143.21) v1(45.01,140.61) v1(45.01,138.05) v1(44.99,100.26) v1(44.99,77.3) v1(45.06,186.18) v1(45.13,166.82) v1(45.08,125.74) v1(45.39,155.24) v1(45.4,130.54) v1(45.49,136.16) v1(45.45,40.29) v1(45.54,24.61) v1(45.64,132.85) v1(45.62,59.56) v1(45.74,158.11) v1(45.67,134.08) v1(45.72,117.88) v1(45.72,115.98) v1(45.75,111.02) v1(45.68,42) v1(45.7,33.66) v1(45.75,165.29) v1(45.83,146.54) v1(45.85,97.42) v1(46.1,16.13) v1(46.1,15.24) v1(46.1,14.35) v1(46.06,10.92) v1(46.22,156.3) v1(46.44,130.07) v1(46.52,188) v1(46.53,149.61) v1(46.48,24.64) v1(46.48,23.83) v1(46.48,22.99) v1(46.61,168.65) v1(46.57,125.83) v1(46.57,124.03) v1(46.56,121.71) v1(46.7,159.14) v1(46.73,127.99) v1(46.68,100.69) v1(46.65,87.33) v1(46.74,28.97) v1(46.8,180.74) v1(46.84,137.5) v1(46.82,10.92) v1(46.91,186.93) v1(46.91,103.92) v1(46.95,130.54) v1(47.03,32.17) v1(47.05,166.76) v1(47.05,163.18) v1(47.09,143.12) v1(47.07,141.34) v1(47.24,160.32) v1(47.18,147.88) v1(47.24,24.64) v1(47.24,23.83) v1(47.28,165.65) v1(47.26,157.3) v1(47.31,144.22) v1(47.25,57.47) v1(47.43,161.36) v1(47.41,145.54) v1(47.37,139.74) v1(47.42,138.8) v1(47.4,135.7) v1(47.4,120.84) v1(47.5,14.86) v1(47.56,186.18) v1(47.58,134.08) v1(47.58,26.3) v1(47.72,129.39) v1(47.74,96.67) v1(47.88,150.95) v1(47.93,146.62) v1(47.9,126.83) v1(47.92,124.48) v1(47.92,122.69) v1(47.9,110.45) v1(48.01,81.03) v1(48.01,56.67) v1(48.01,23.88) v1(48.1,132.48) v1(48.12,108.91) v1(48.15,102.72) v1(48.14,85.96) v1(48.08,74.45) v1(48.06,24.64) v1(48.13,22.61) v1(48.35,158.58) v1(48.45,186.18) v1(48.38,123.11) v1(48.38,119.8) v1(48.38,117.9) v1(48.45,27.93) v1(48.39,14.86) v1(48.53,149.23) v1(48.5,130.31) v1(48.55,128.69) v1(48.48,105.01) v1(48.56,147.98) v1(48.64,25.15) v1(48.66,184.53) v1(48.72,170.41) v1(48.74,137.05) v1(48.68,87.33) v1(48.76,176.84) v1(48.78,118.76) v1(48.76,102.08) v1(48.77,4.95) v1(48.95,160.04) v1(49.03,32.75) v1(49.06,161.37) v1(49.05,138.89) v1(49.15,135.81) v1(49.23,152.3) v1(49.23,130.25) v1(49.34,186.18) v1(49.35,127.56) v1(49.43,163.22) v1(49.39,142.59) v1(49.39,140.68) v1(49.48,165.64) v1(49.48,134.08) v1(49.53,5.59) v1(49.61,149.03) v1(49.56,132.42) v1(49.56,110.16) v1(49.63,106.96) v1(49.61,27.78) v1(49.66,146.21) v1(49.84,126.36) v1(49.78,26.54) v1(49.78,25.78) v1(49.87,150.58) v1(49.86,117.37) v1(49.95,171.67) v1(50.02,124.71) v1(50.04,122.4) v1(50.02,120.56) v1(50.13,136.81) v1(50.14,108.82) v1(50.22,147.33) v1(50.15,86.57) v1(50.2,81.85) v1(50.22,53.06) v1(50.32,166.61) v1(50.29,103.28) v1(50.29,25.15) v1(50.36,169.06) v1(50.42,4.95) v1(50.58,153.65) v1(50.58,130.4) v1(50.64,99.9) v1(50.62,96.15) v1(50.72,146) v1(50.71,132.02) v1(50.72,32.01) v1(50.99,94.09) v1(50.97,87.33) v1(51.13,149.77) v1(51.06,137.75) v1(51.14,85.96) v1(51.17,164.79) v1(51.22,151.92) v1(51.19,143.54) v1(51.21,135.7) v1(51.32,129.41) v1(51.35,59.25) v1(51.4,169.73) v1(51.39,134.08) v1(51.37,123.36) v1(51.39,121.05) v1(51.37,119.22) v1(51.4,116.54) v1(51.4,105.58) v1(51.36,70.94) v1(51.36,61.32) v1(51.47,148.15) v1(51.52,107.44) v1(51.52,81.87) v1(51.51,67.41) v1(51.63,97.54) v1(51.65,28.15) v1(51.95,171.52) v1(51.92,154.52) v1(51.94,23.75) v1(51.94,22.86) v1(52.03,127.69) v1(52.05,33.66) v1(51.99,26.47) v1(52.06,136.44) v1(52.11,131.56) v1(52.11,115.08) v1(52.12,76.05) v1(52.18,182.09) v1(52.23,43.27) v1(52.32,174) v1(52.31,113.49) v1(52.31,111.58) v1(52.31,109.68) v1(52.31,107.77) v1(52.32,104.49) v1(52.26,46.11) v1(52.44,152.9) v1(52.4,101.24) v1(52.74,169.83) v1(52.66,145.83) v1(52.68,139.32) v1(52.72,122.02) v1(52.74,119.71) v1(52.77,32.6) v1(52.95,137.29) v1(52.88,99.54) v1(52.87,67.61) v1(52.96,129.96) v1(53.02,126.92) v1(52.99,85.38) v1(53.01,58.32) v1(53.14,167.29) v1(53.11,135.7) v1(53.17,149.88) v1(53.25,81.85) v1(53.29,134.08) v1(53.39,148.24) v1(53.5,116.19) v1(53.45,27.95) v1(53.56,97.26) v1(53.72,155.13) v1(53.76,171.49) v1(53.77,128.41) v1(53.94,169.73) v1(53.94,139.65) v1(53.89,114.69) v1(53.96,153.48) v1(53.98,137.91) v1(53.96,112.78) v1(53.96,110.87) v1(53.96,108.97) v1(53.97,106.72) v1(53.98,105.06) v1(53.98,103.15) v1(54.11,175.8) v1(54.06,120.67) v1(54.08,118.36) v1(54.05,97.97) v1(54.29,81.85) v1(54.28,48.4) v1(54.27,33.66) v1(54.41,126.65) v1(54.42,101.31) v1(54.45,68.01) v1(54.42,44.13) v1(54.46,66.6) v1(54.46,65.07) v1(54.54,55.95) v1(54.6,86.62) v1(54.6,63.82) v1(54.58,62.02) v1(54.6,60.96) v1(54.58,59.16) v1(54.73,174.27) v1(54.79,97.49) v1(54.91,69.44) v1(55.02,135.7) v1(55.03,87.33) v1(55.07,149.88) v1(55.15,71.05) v1(55.24,171.48) v1(55.2,134.08) v1(55.28,168.93) v1(55.26,147.36) v1(55.41,119.32) v1(55.41,99.48) v1(55.4,96.57) v1(55.42,58.49) v1(55.42,56.59) v1(55.42,54.68) v1(55.42,52.78) v1(55.42,50.87) v1(55.4,49.41) v1(55.46,155.29) v1(55.49,153.64) v1(55.53,93.21) v1(55.46,76.75) v1(55.57,128.29) v1(55.82,67.81) v1(55.91,177.6) v1(55.91,140.01) v1(55.94,137.48) v1(55.88,126.07) v1(55.88,106.72) v1(55.88,104.5) v1(55.91,71.25) v1(55.98,95.03) v1(55.98,69.09) v1(56.01,63.74) v1(56.07,85.4) v1(56.11,66.57) v1(56.11,65.05) v1(56.14,62.1) v1(56.14,60.76) v1(56.31,36.13) v1(56.3,33.66) v1(56.53,176.06) v1(56.47,149.91) v1(56.51,128.89) v1(56.54,118.42) v1(56.63,112.81) v1(56.6,95.12) v1(56.67,93.51) v1(56.84,169.71) v1(56.83,148.21) v1(56.76,98.14) v1(56.95,153.62) v1(56.92,135.7) v1(56.96,134.08) v1(56.99,104.6) v1(57.04,45.98) v1(57.07,126.17) v1(57.05,59.72) v1(57.05,57.82) v1(57.05,55.91) v1(57.05,54.01) v1(57.05,52.1) v1(57.05,50.2) v1(57.1,48.77) v1(57.16,116.08) v1(57.28,114.34) v1(57.26,87.33) v1(57.36,155.29) v1(57.52,71.75) v1(57.59,179.17) v1(57.73,139.59) v1(57.69,74.41) v1(57.78,69.67) v1(57.78,66.87) v1(57.77,64.78) v1(57.81,63.27) v1(57.78,26.16) v1(57.89,136.4) v1(58.01,137.86) v1(58.2,164.65) v1(58.16,117.93) v1(58.18,25.21) v1(58.3,94.64) v1(58.37,177.82) v1(58.36,97.18) v1(58.49,133.8) v1(58.47,112.24) v1(58.47,47.85) v1(58.53,44.04) v1(58.54,42.47) v1(58.54,40.56) v1(58.54,38.66) v1(58.54,36.75) v1(58.51,35.13) v1(58.51,33.22) v1(58.51,31.32) v1(58.51,29.41) v1(58.55,27.56) v1(58.56,92.71) v1(58.64,62.53) v1(58.72,115.4) v1(58.71,73.04) v1(58.67,63.98) v1(58.67,60.48) v1(58.67,58.57) v1(58.67,56.67) v1(58.67,54.76) v1(58.67,52.86) v1(58.69,46.66) v1(58.81,119.81) v1(58.8,70.64) v1(58.76,66.6) v1(58.78,50.93) v1(58.89,136.98) v1(59.05,25.65) v1(59.27,155.29) v1(59.31,139.09) v1(59.29,87.33) v1(59.38,56.99) v1(59.39,45.92) v1(59.46,49.61) v1(59.66,145.11) v1(59.71,117.16) v1(60.02,74.23) v1(60.12,179.4) v1(60.15,41.9) v1(60.15,39.99) v1(60.15,38.09) v1(60.15,36.18) v1(60.15,34.28) v1(60.15,32.37) v1(60.15,30.47) v1(60.23,138.09) v1(60.16,96.66) v1(60.2,94.56) v1(60.17,43.22) v1(60.16,28.56) v1(60.23,23.82) v1(60.3,62.31) v1(60.33,59.38) v1(60.39,167.36) v1(60.38,64.19) v1(60.38,60.4) v1(60.52,92.83) v1(60.6,137.01) v1(60.6,134.09) v1(60.55,113.01) v1(60.55,69.75) v1(60.55,26.67) v1(60.78,135.73) v1(60.77,114) v1(60.76,45.29) v1(60.82,42.81) v1(60.91,177.88) v1(60.94,116.44) v1(60.91,114.78) v1(60.89,87.55) v1(60.89,86.54) v1(60.88,41.15) v1(61.12,55.9) v1(61.17,155.29) v1(61.15,94.96) v1(61.24,73.13) v1(61.2,57.65) v1(61.16,47.83) v1(61.37,68.53) v1(61.42,39.7) v1(61.65,22.33) v1(61.85,35.04) v1(61.77,32.53) v1(61.91,76.03) v1(61.91,24.36) v1(62.08,30.17) v1(62.16,96.6) v1(62.28,117.94) v1(62.37,74.26) v1(62.48,88.91) v1(62.48,45.53) v1(62.48,43.62) v1(62.47,41.61) v1(62.64,135.7) v1(62.65,114.55) v1(62.66,179.4) v1(62.8,116.19) v1(62.84,55.84) v1(62.82,34.03) v1(62.82,33.02) v1(62.99,37.96) v1(62.99,20.98) v1(63.08,155.29) v1(63.06,94.96) v1(63.13,40.14) v1(63.19,57.49) v1(63.37,22.91) v1(63.87,75.02) v1(64.07,96.6) v1(64.34,19.63) v1(64.54,135.7) v1(64.47,36.68) v1(64.7,116.19) v1(64.66,114.52) v1(64.66,38.67) v1(64.66,21.59) v1(64.92,134.09) v1(64.94,57.49) v1(64.98,155.29) v1(64.96,94.96) v1(65.02,55.84) v1(65.17,179.25) v1(65.2,136.58) v1(65.18,77.04) v1(65.39,75.39) v1(65.63,177.25) v1(65.69,18.28) v1(65.76,153.63) v1(66.04,182.02) v1(66.01,136.19) v1(65.97,96.6) v1(66.01,20.24) v1(66.18,37.95) v1(66.45,135.7) v1(66.37,36.3) v1(66.54,53.17) v1(66.61,116.19) v1(66.57,114.52) v1(66.59,55.82) v1(66.57,54.21) v1(66.72,133.14) v1(66.83,134.09) v1(66.78,109.25) v1(66.89,155.29) v1(66.87,94.96) v1(67.06,177.97) v1(67.08,77.04) v1(67.3,75.39) v1(67.33,57.47) v1(67.43,175.45) v1(67.39,131.7) v1(67.39,130.68) v1(67.39,90.27) v1(67.39,89.25) v1(67.36,18.89) v1(67.44,16.89) v1(67.56,110.9) v1(67.87,153.62) v1(67.88,96.6) v1(68.05,37.91) v1(68.3,110.66) v1(68.29,36.29) v1(68.33,33.17) v1(68.33,32.15) v1(68.43,171.22) v1(68.43,170.2) v1(68.36,151.71) v1(68.36,150.7) v1(68.35,135.7) v1(68.38,131.72) v1(68.38,130.71) v1(68.41,90.27) v1(68.41,89.25) v1(68.51,116.19) v1(68.47,114.52) v1(68.5,55.82) v1(68.73,134.09) v1(68.79,155.29) v1(68.77,94.96) v1(68.85,185.75) v1(68.86,176.18) v1(68.86,18.36) v1(68.86,16.74) v1(69.04,152.55) v1(68.99,77.04) v1(69.06,132.99) v1(69.07,111.99) v1(69.07,110.97) v1(69.09,52.48) v1(69.09,51.47) v1(69.2,75.39) v1(69.24,57.47) v1(69.35,33.17) v1(69.35,32.15) v1(69.34,10.92) v1(69.34,9.14) v1(69.34,4.7) v1(69.34,3.17) v1(69.43,173.89) v1(69.45,171.22) v1(69.45,170.2) v1(69.37,151.71) v1(69.37,150.7) v1(69.4,131.72) v1(69.4,130.71) v1(69.42,58.39) v1(69.52,153.64) v1(69.78,96.6) v1(69.85,11.68) v1(69.85,10.03) v1(69.85,3.94) v1(69.85,2.41) v1(69.89,116.17) v1(69.91,77.05) v1(70.02,155.28) v1(69.95,135.71) v1(69.95,37.91) v1(70,18.37) v1(70.08,111.99) v1(70.08,110.97) v1(70.11,52.48) v1(70.11,51.47) v1(70.19,71.83) v1(70.19,70.81) v1(70.19,69.8) v1(70.19,68.78) v1(70.19,36.29) v1(70.42,55.84) v1(70.46,153.27) v1(70.47,133.73) v1(70.5,114.17) v1(70.49,94.61) v1(70.5,75.35) v1(70.5,16.71) v1(70.63,167.2) v1(70.91,128.18) v1(71.14,110.39) v1(71.29,175.25) v1(71.37,132.99) v1(71.4,54.69) v1(71.44,16.21) v1(71.45,113.39) v1(71.49,93.9) v1(71.53,74.87) v1(71.46,35.79) v1(71.56,149.51) v1(71.74,180.72) v1(71.69,153.09) v1(71.71,33.29) v1(71.96,173.72) v1(72.58,171.51) v1(72.58,130.87) v1(72.92,78.16) v1(72.92,58.6) v1(72.92,39.04) v1(72.92,19.48) v1(73.06,16.51) v1(73.33,98.12) v1(73.36,156.85) v1(73.43,137.45) v1(73.36,117.45) v1(73.42,111.76) v1(73.71,133.73) v1(73.71,75.06) v1(73.71,55.5) v1(73.71,35.94) v1(73.89,114.15) v1(73.99,94.72) v1(74.17,156.39) v1(74.3,97.71) v1(74.4,117.27) v1(74.45,78.16) v1(74.45,58.6) v1(74.45,39.04) v1(74.45,19.48) v1(74.5,173.72) v1(74.47,136.83) v1(74.57,153.29) v1(74.68,75.03) v1(74.68,55.47) v1(74.68,35.92) v1(74.68,16.36) v1(75.94,164.16) v1(75.94,144.53) v1(75.94,124.49) v1(75.94,104.94) v1(75.94,85.63) v1(75.94,66.32) v1(75.94,46.87) v1(75.94,28.02) v1(75.96,165.2) v1(75.96,145.57) v1(75.96,125.53) v1(75.96,105.98) v1(75.96,86.67) v1(75.96,67.36) v1(75.96,47.91) v1(75.96,29.06) v1(76.49,175.2) v1(76.46,130.18) v1(76.98,165.2) v1(76.98,145.57) v1(76.98,125.53) v1(76.98,105.98) v1(76.98,86.67) v1(76.98,67.36) v1(76.98,47.91) v1(76.98,29.06) v1(77.12,140.33) v1(77.24,159.62) v1(77.22,158.69) v1(77.16,139.43) v1(77.18,100.65) v1(77.33,120.27) v1(77.43,153.16) v1(77.37,119.37) v1(77.38,114.04) v1(77.41,33.17) v1(77.41,22.67) v1(77.48,156.5) v1(77.45,97.8) v1(77.54,39.12) v1(77.62,133.59) v1(77.64,117.38) v1(77.61,94.48) v1(77.57,78.25) v1(77.61,74.93) v1(77.55,58.69) v1(77.59,55.38) v1(77.6,35.8) v1(77.61,19.58) v1(77.64,16.25) v1(77.69,136.94) v1(77.76,110.77) v1(77.91,53.53) v1(78.08,160.46) v1(78.14,140.33) v1(78.11,101.41) v1(78.15,100.52) v1(78.14,71.88) v1(78.18,139.43) v1(78.35,120.27) v1(78.39,119.37) v1(78.36,103.17) v1(78.37,91.52) v1(78.59,169.54) v1(78.74,122.89) v1(78.74,64.69) v1(78.71,45.29) v1(78.77,162.66) v1(78.77,142.98) v1(78.77,84.02) v1(78.77,26.39) v1(78.9,151.27) v1(78.9,61.53) v1(78.86,21.75) v1(79.13,101.41) v1(79.05,80.71) v1(79.14,55.38) v1(79.15,35.8) v1(79.19,136.96) v1(79.17,100.52) v1(79.16,74.93) v1(79.24,39.12) v1(79.19,16.25) v1(79.31,156.53) v1(79.27,133.61) v1(79.27,78.25) v1(79.25,58.69) v1(79.31,19.58) v1(79.43,153.14) v1(79.44,117.4) v1(79.41,114.04) v1(79.42,94.48) v1(79.43,41.81) v1(79.46,97.8) v1(79.58,180.27) v1(80.31,32.75) v1(80.38,23.89) v1(80.5,130.72) v1(80.5,43.79) v1(80.84,154.88) v1(80.8,140.61) v1(80.95,110.16)
